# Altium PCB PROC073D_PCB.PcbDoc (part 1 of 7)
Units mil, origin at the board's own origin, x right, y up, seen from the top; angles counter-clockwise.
Board outline 2165.35 x 2695.12 mil, 8 copper layers (Top Layer, L2_GND, L3_SIGNAL 1, L4_SIGNAL 2, L5_SIGNAL 3, L6_SIGNAL 4, L7_GND, Bottom Layer), stack 56.1 mil thick; 414 components, 319 nets, 1353 pads, 1669 vias.
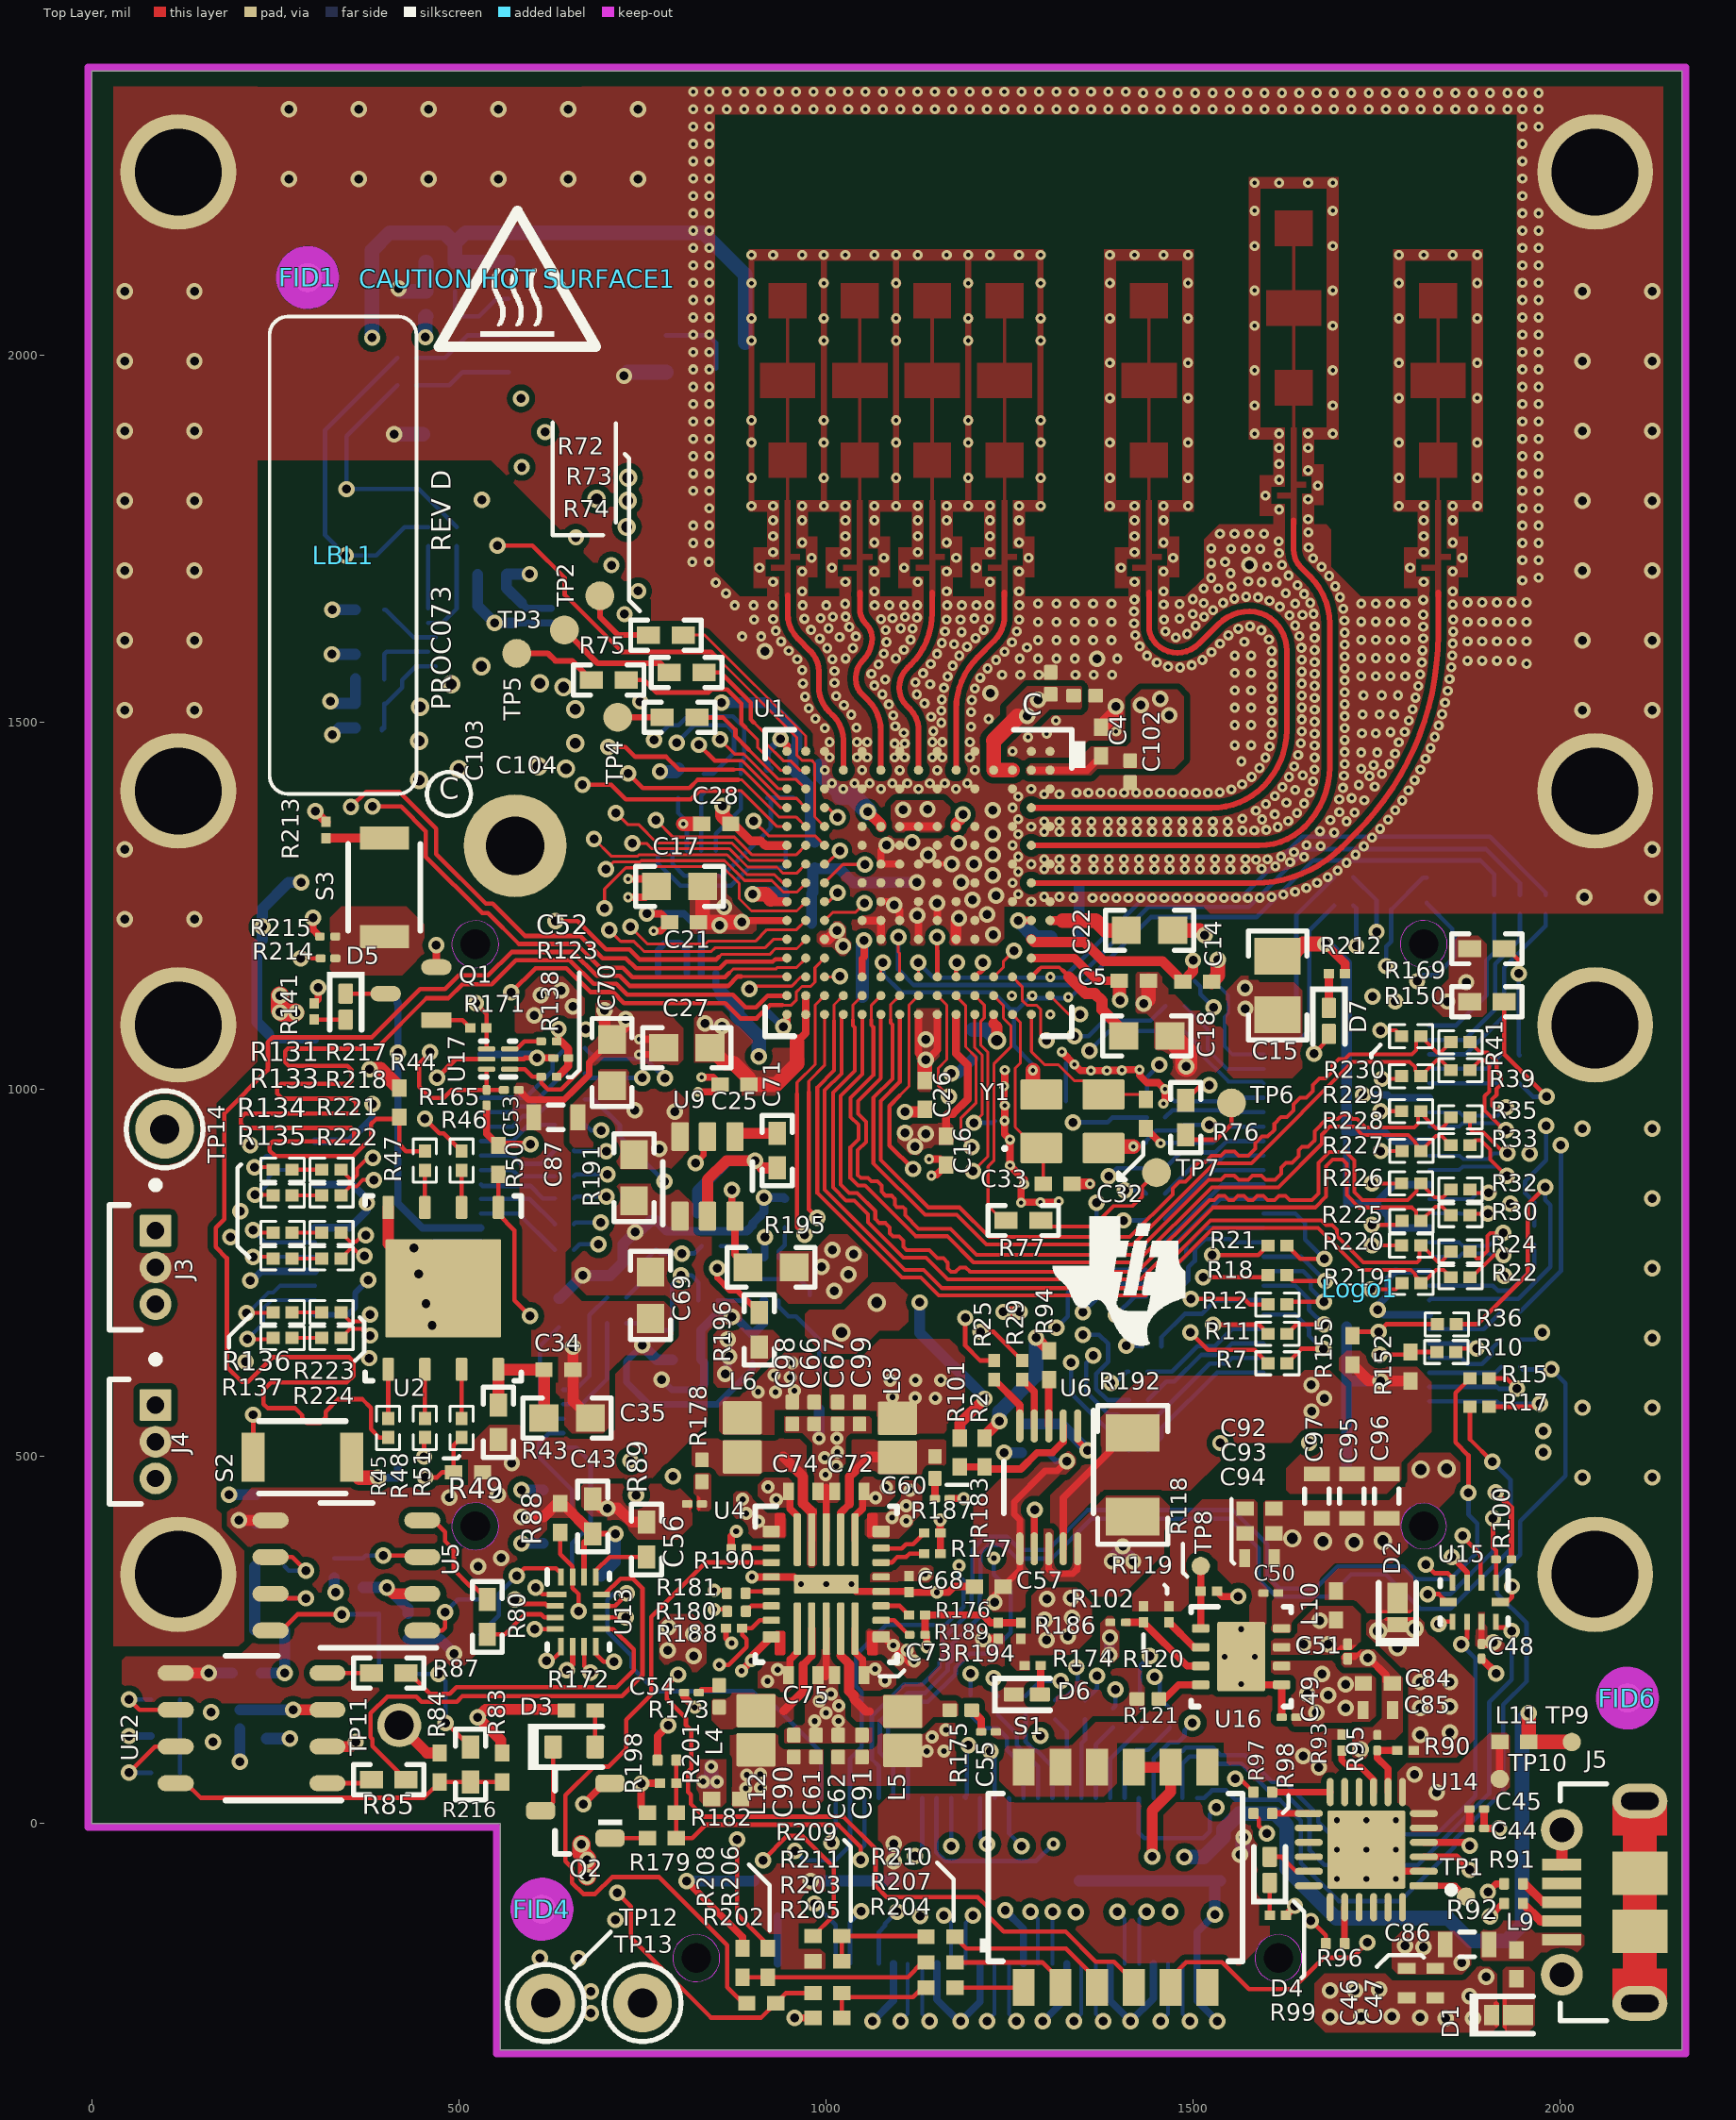
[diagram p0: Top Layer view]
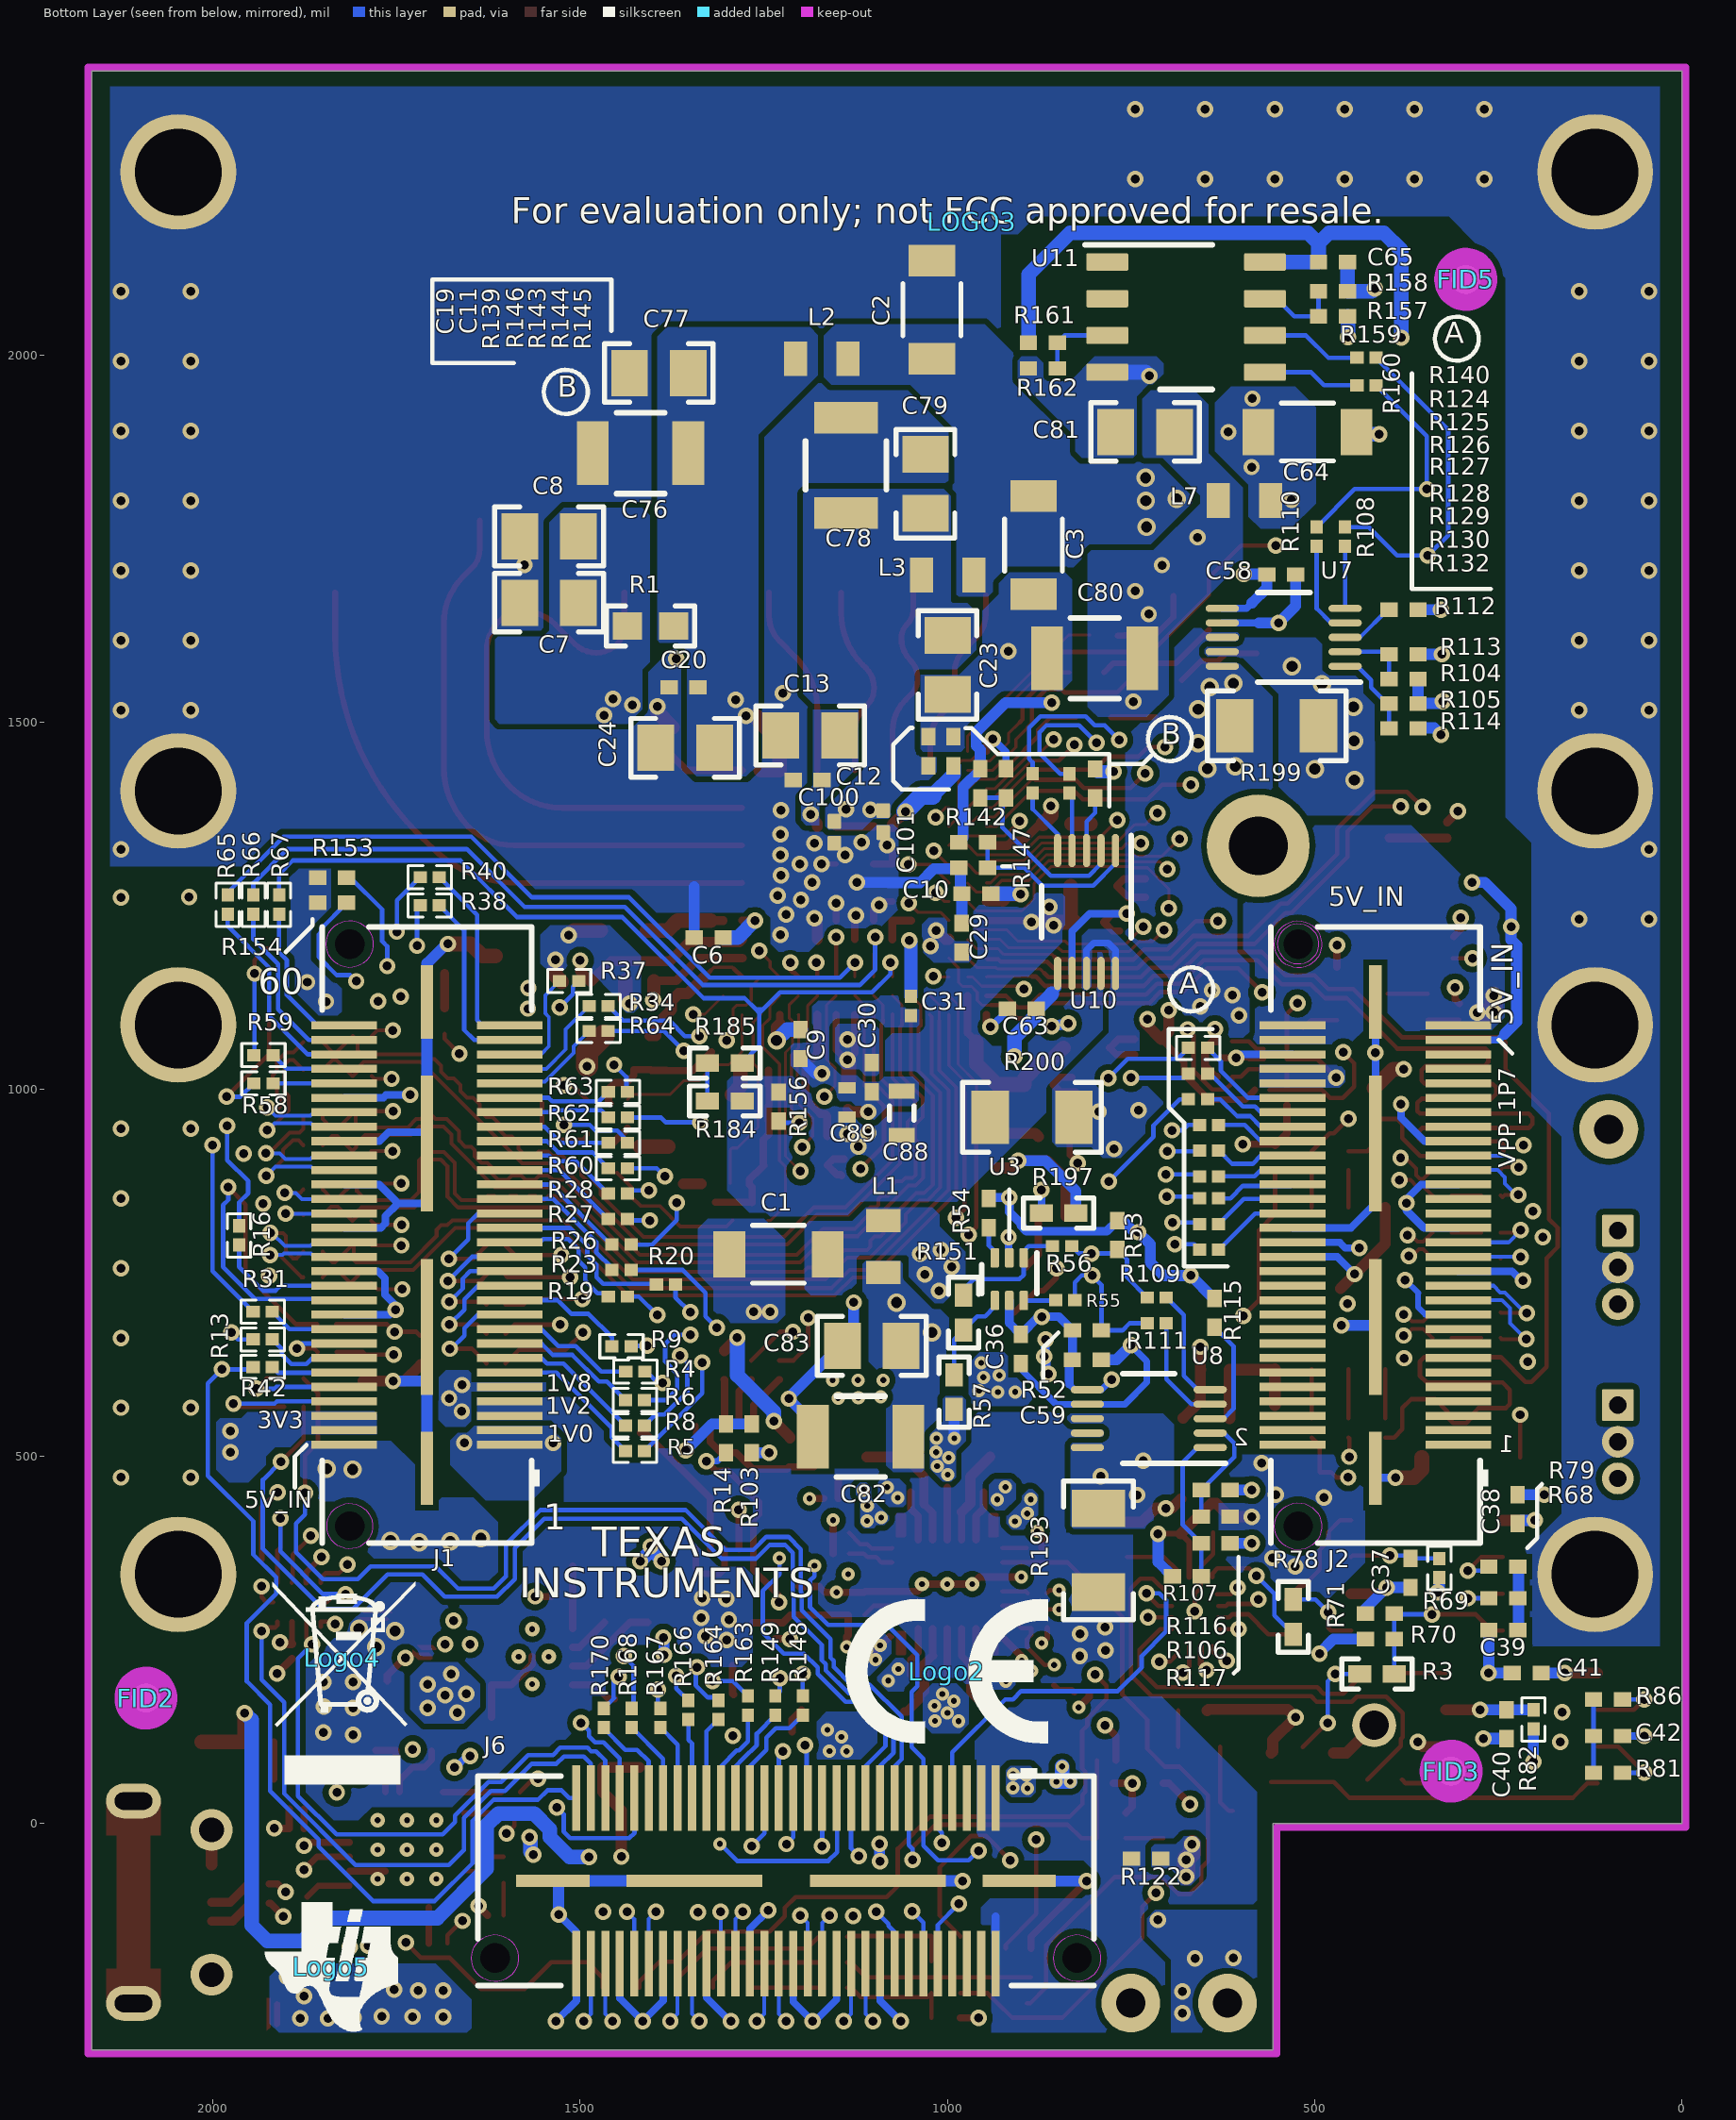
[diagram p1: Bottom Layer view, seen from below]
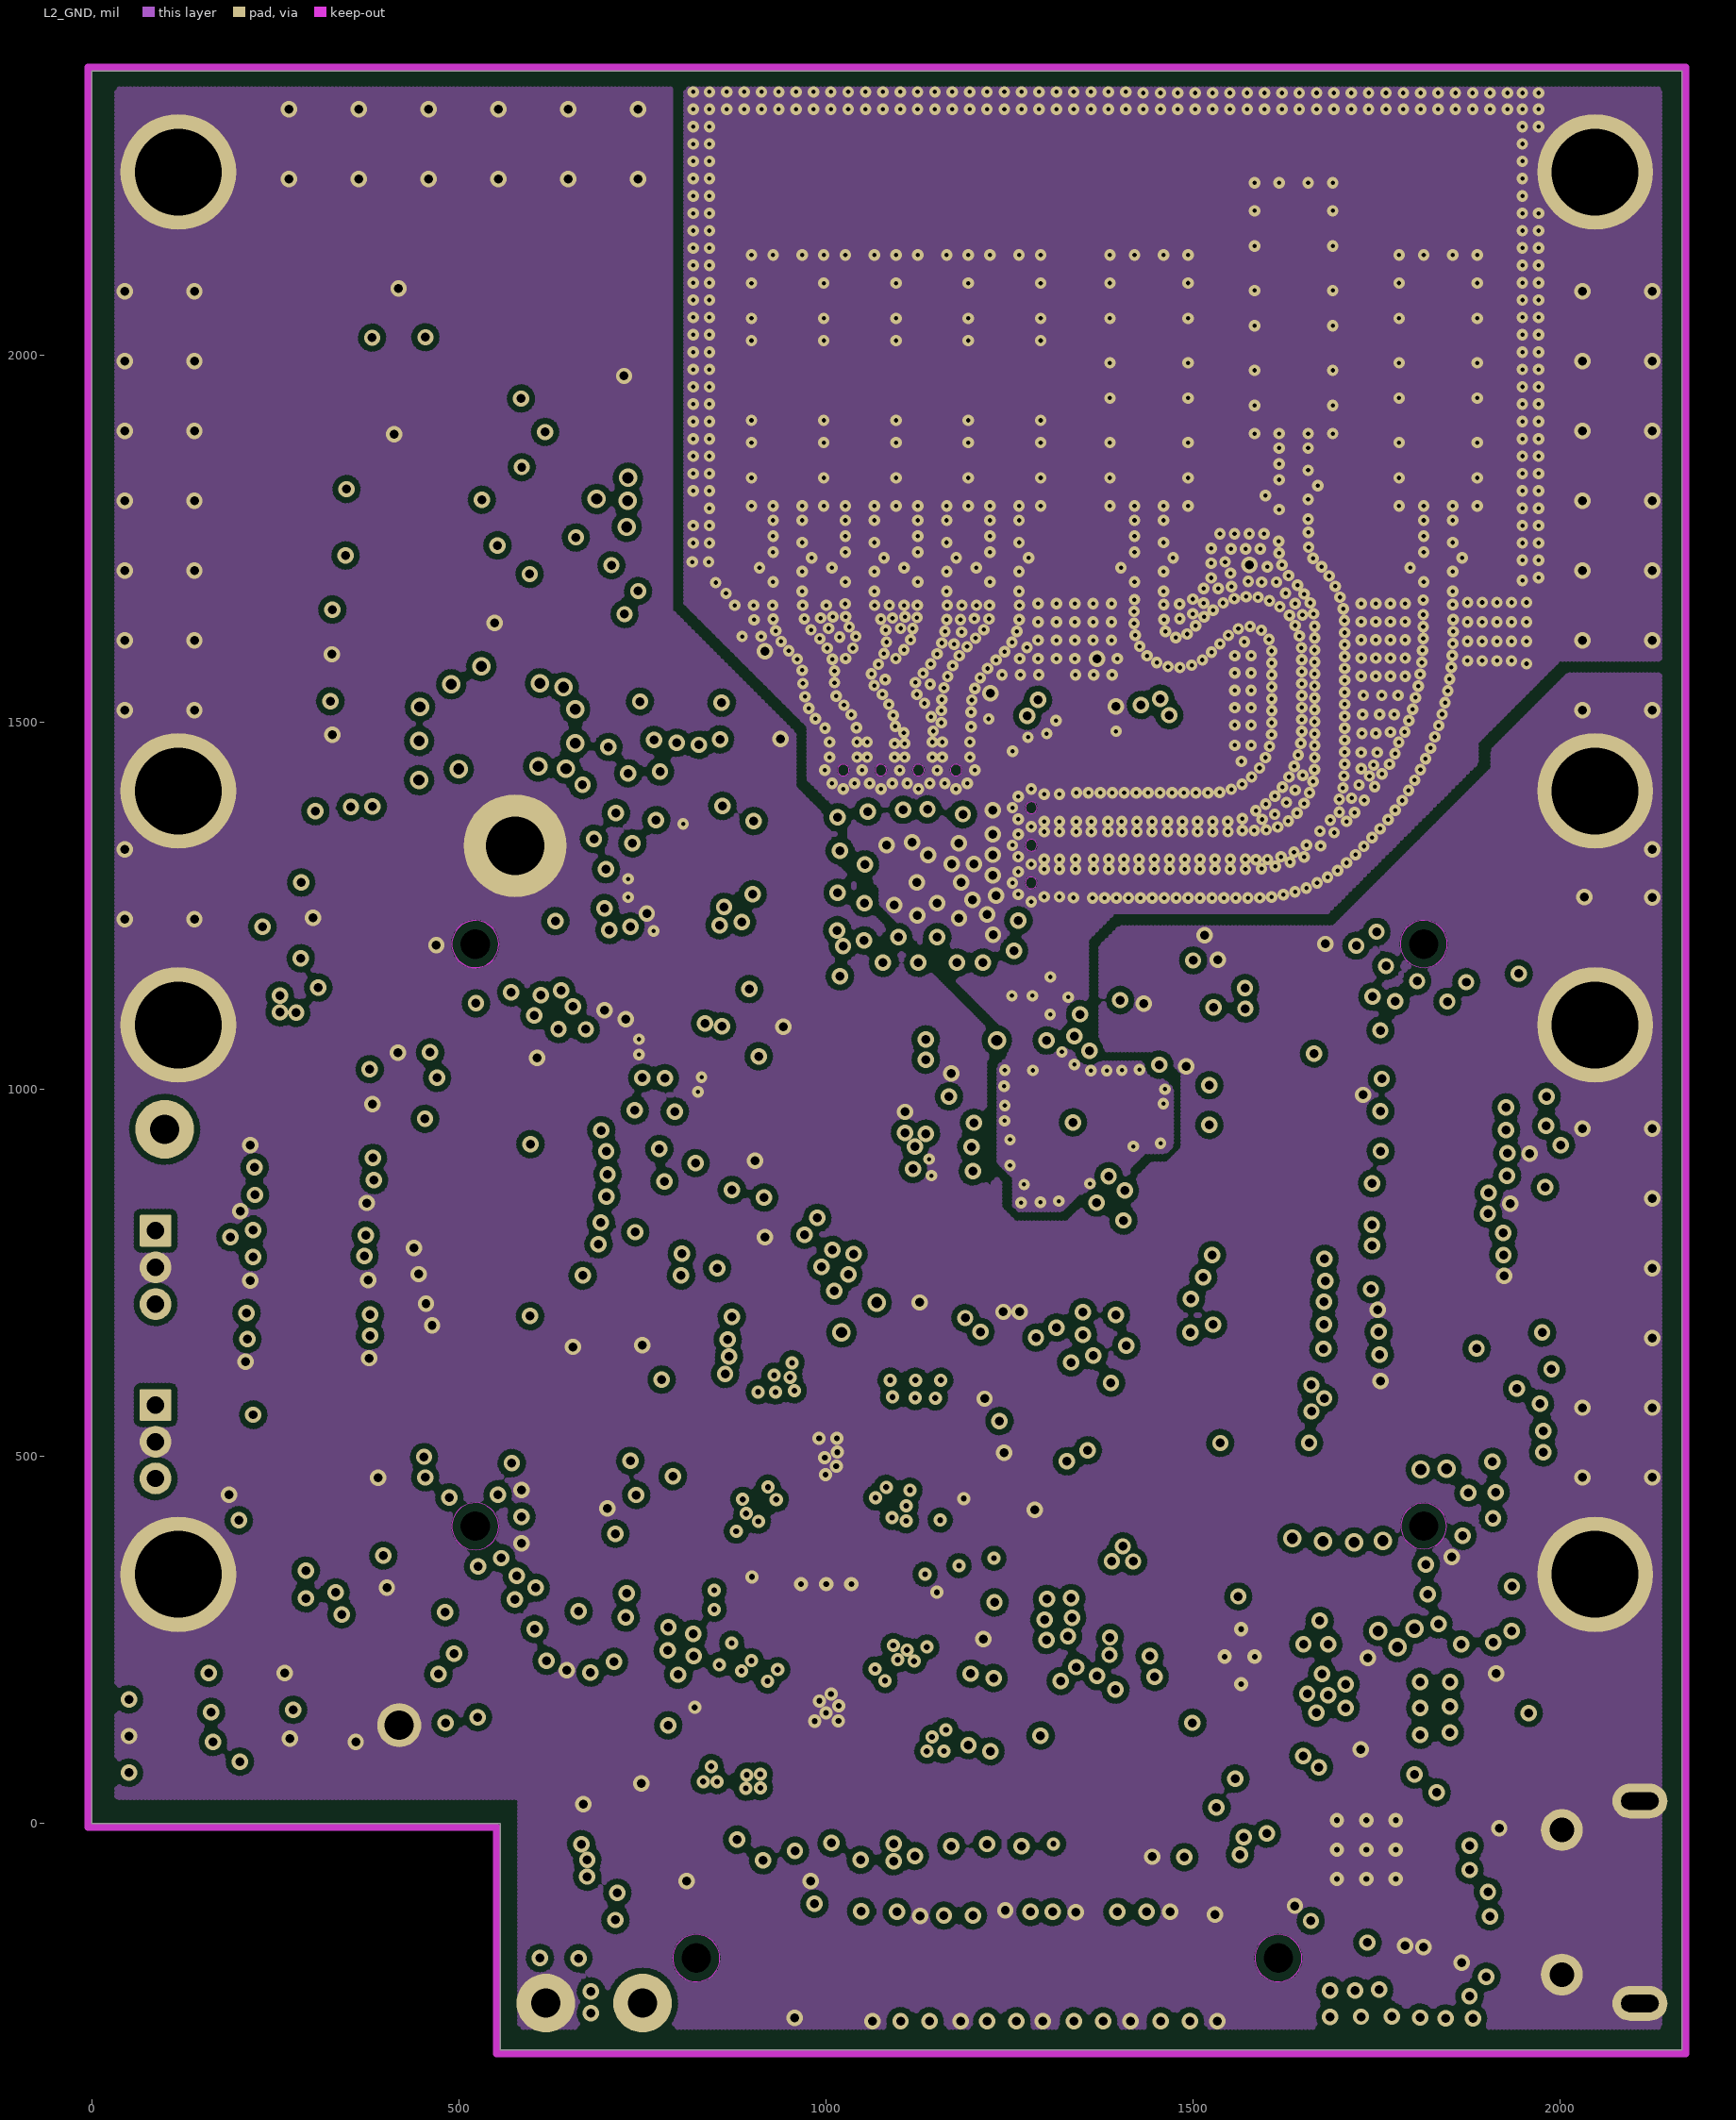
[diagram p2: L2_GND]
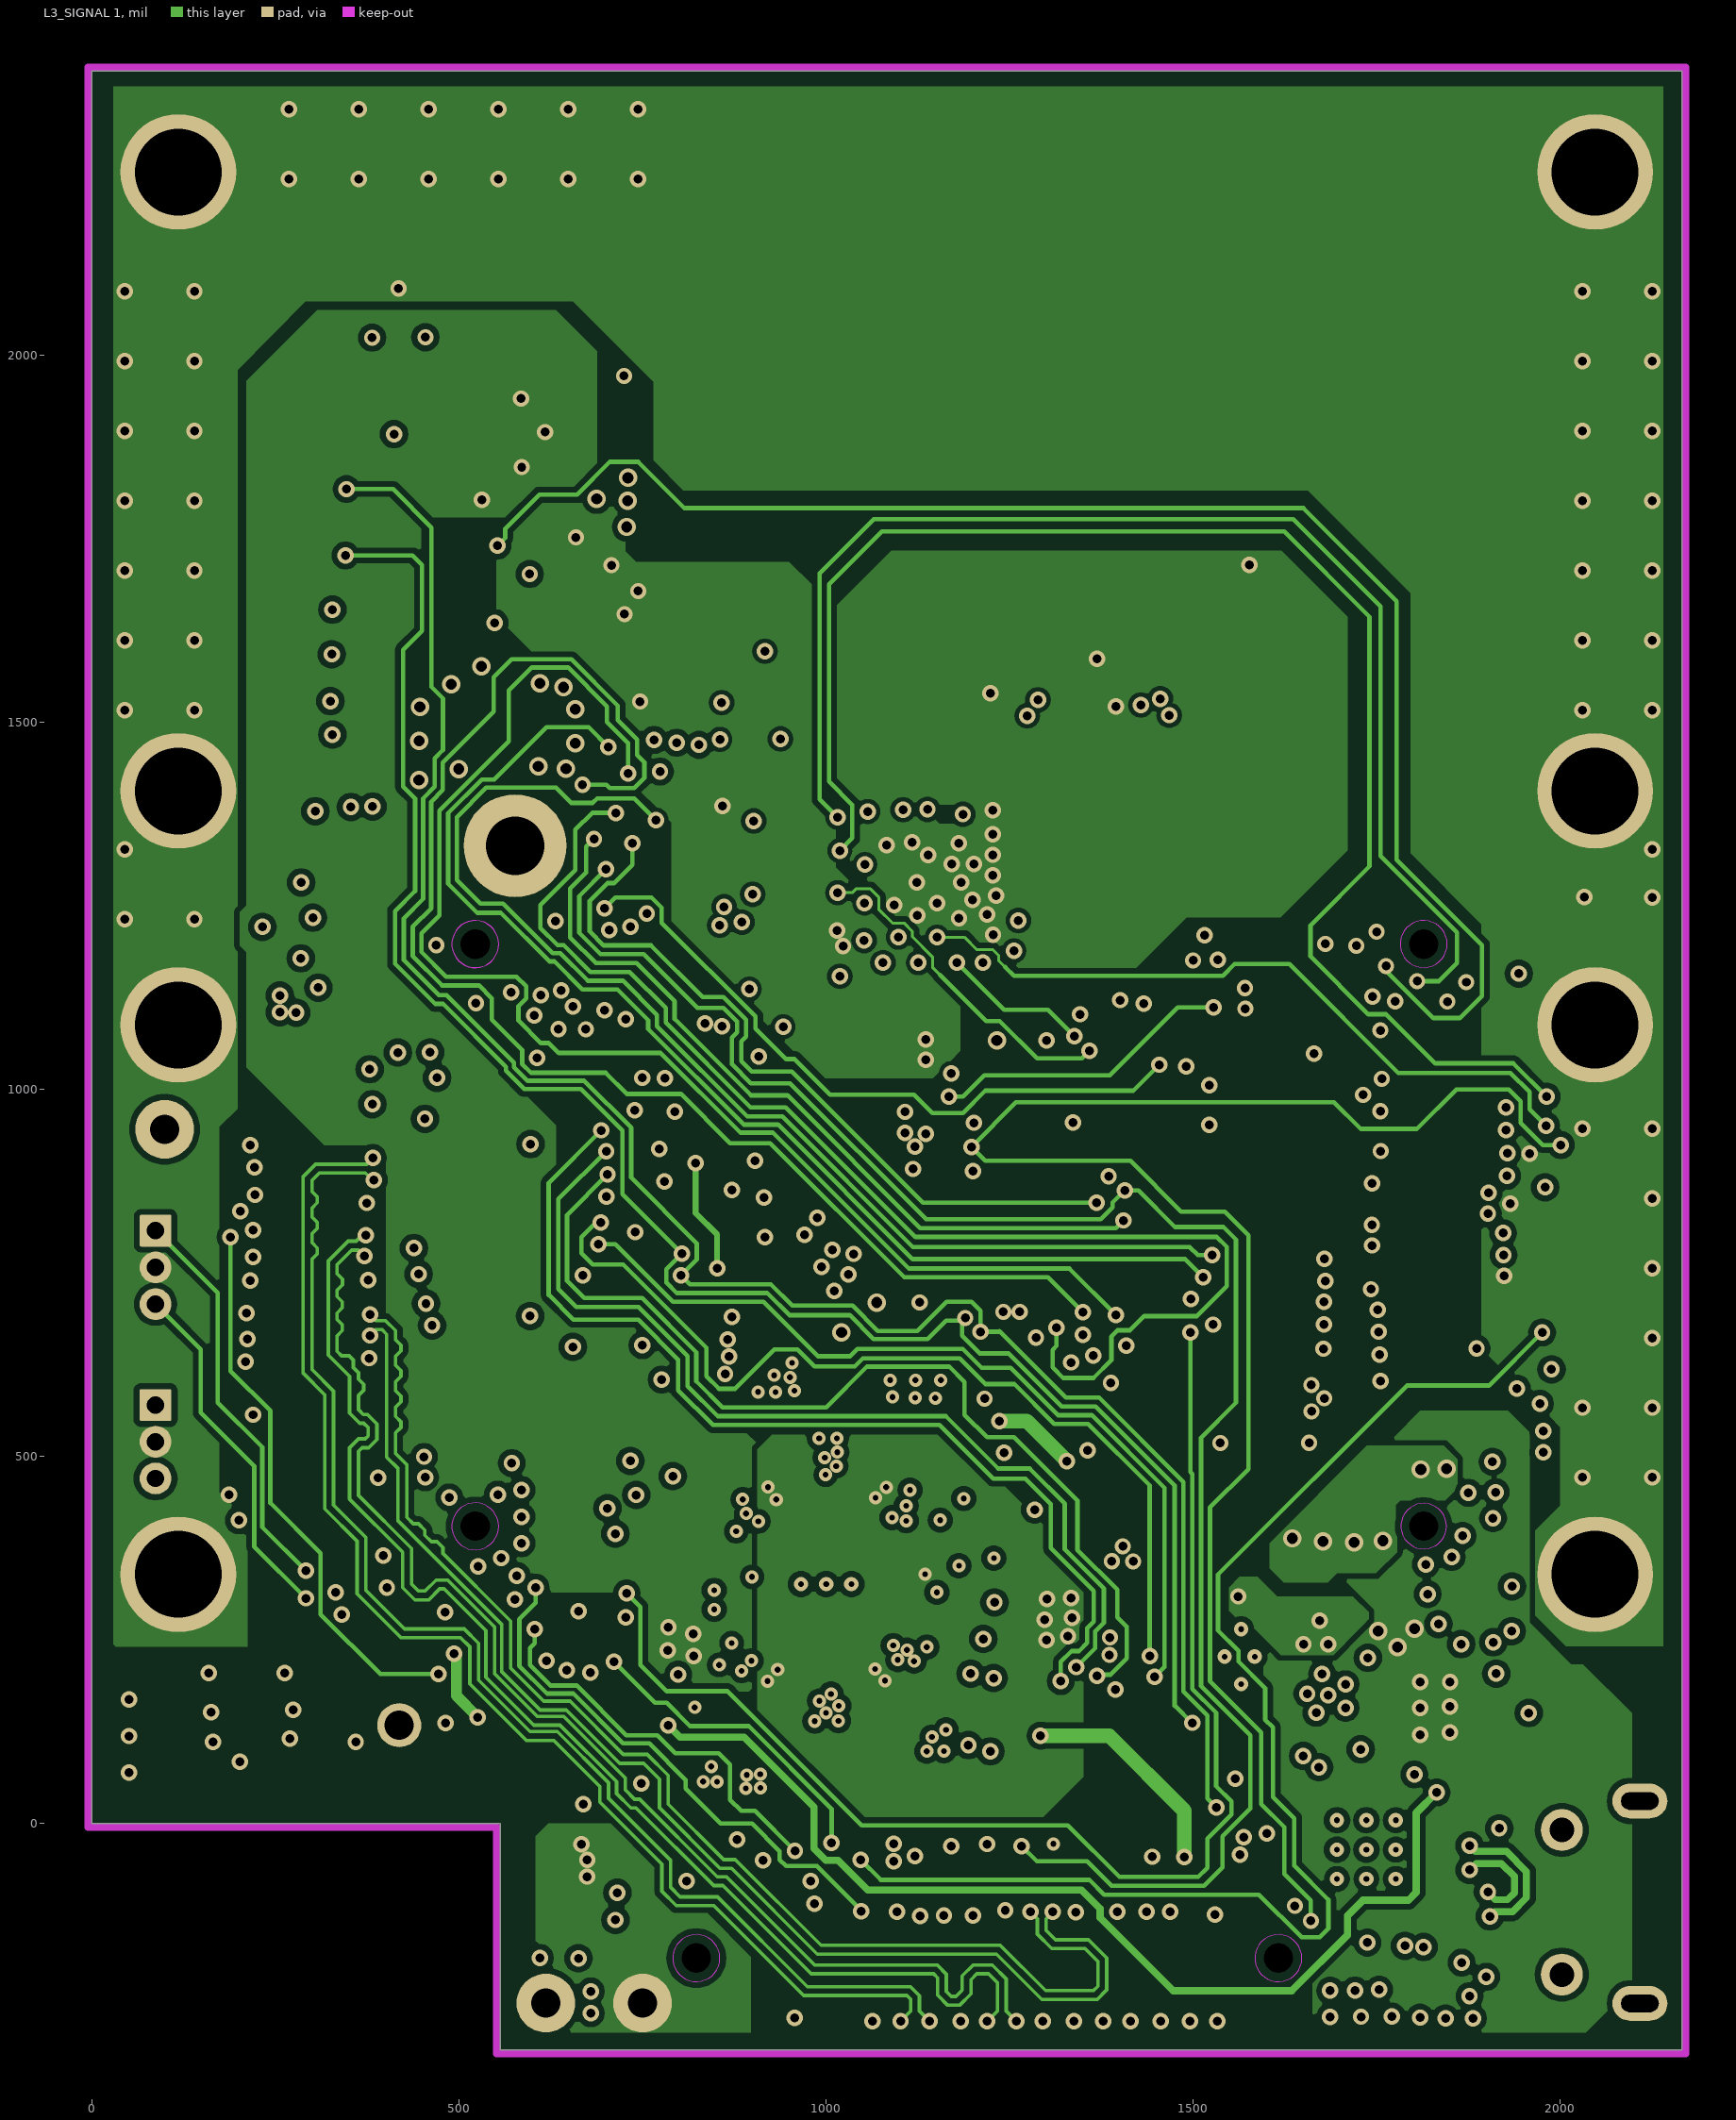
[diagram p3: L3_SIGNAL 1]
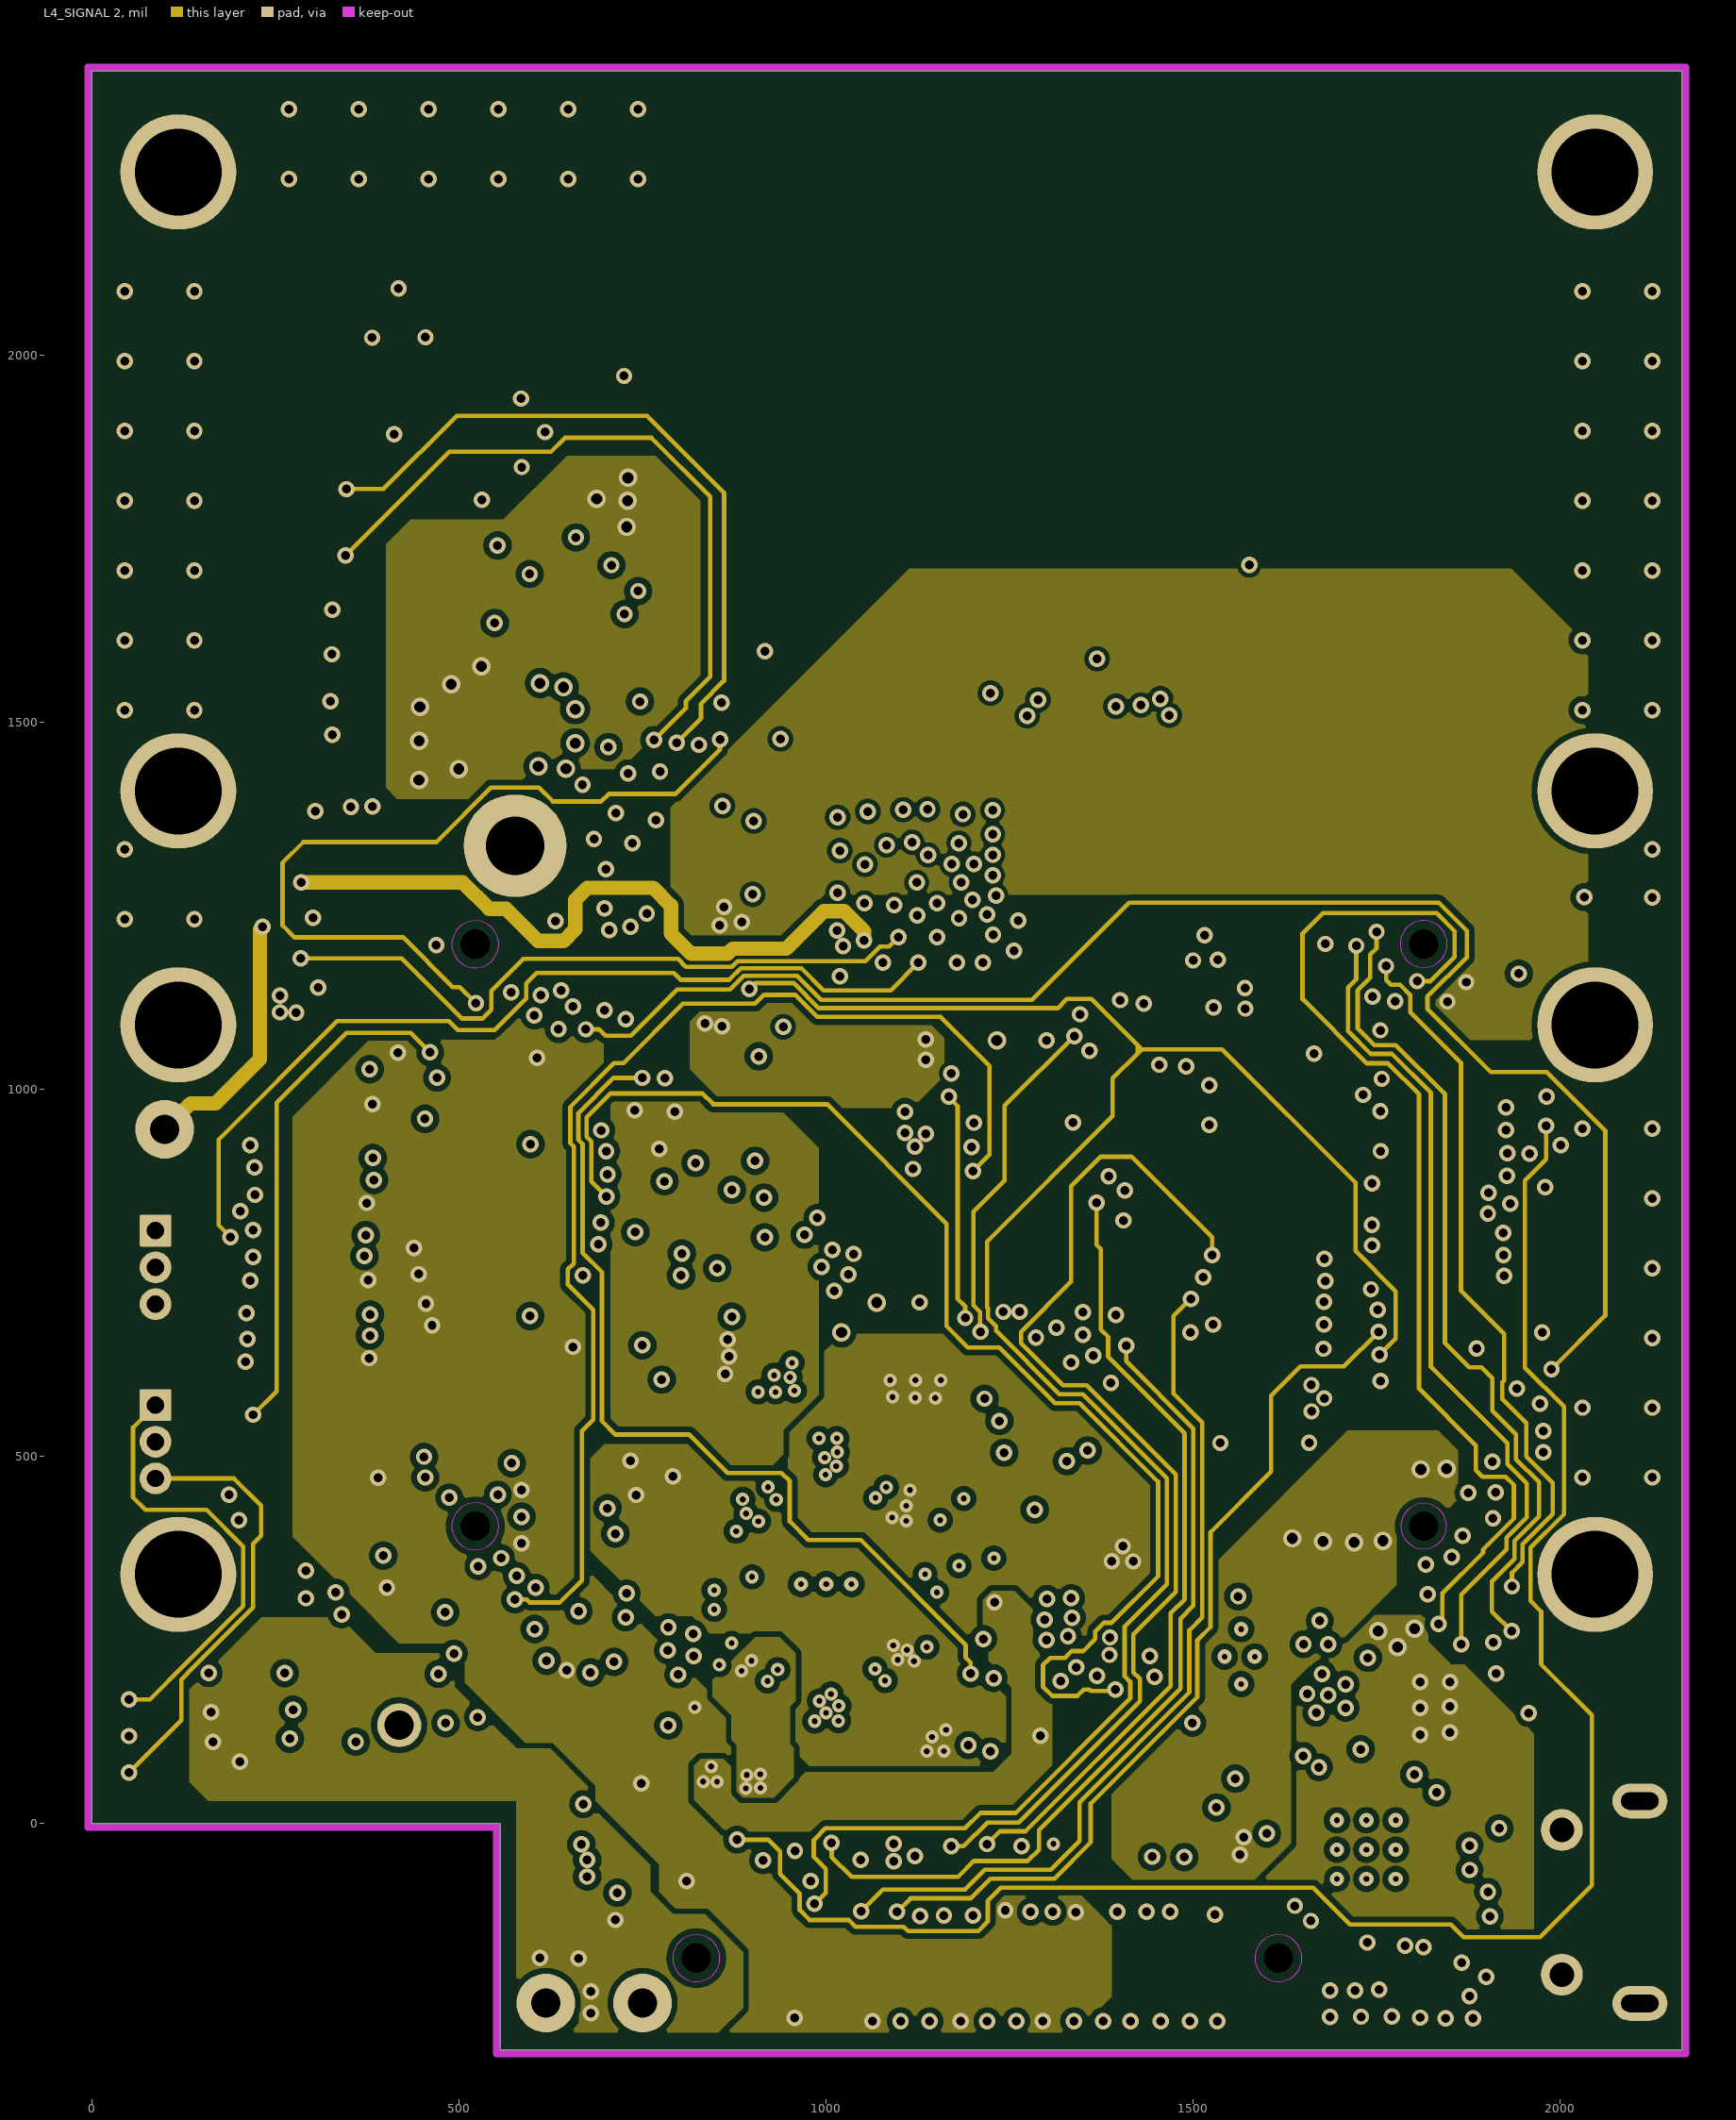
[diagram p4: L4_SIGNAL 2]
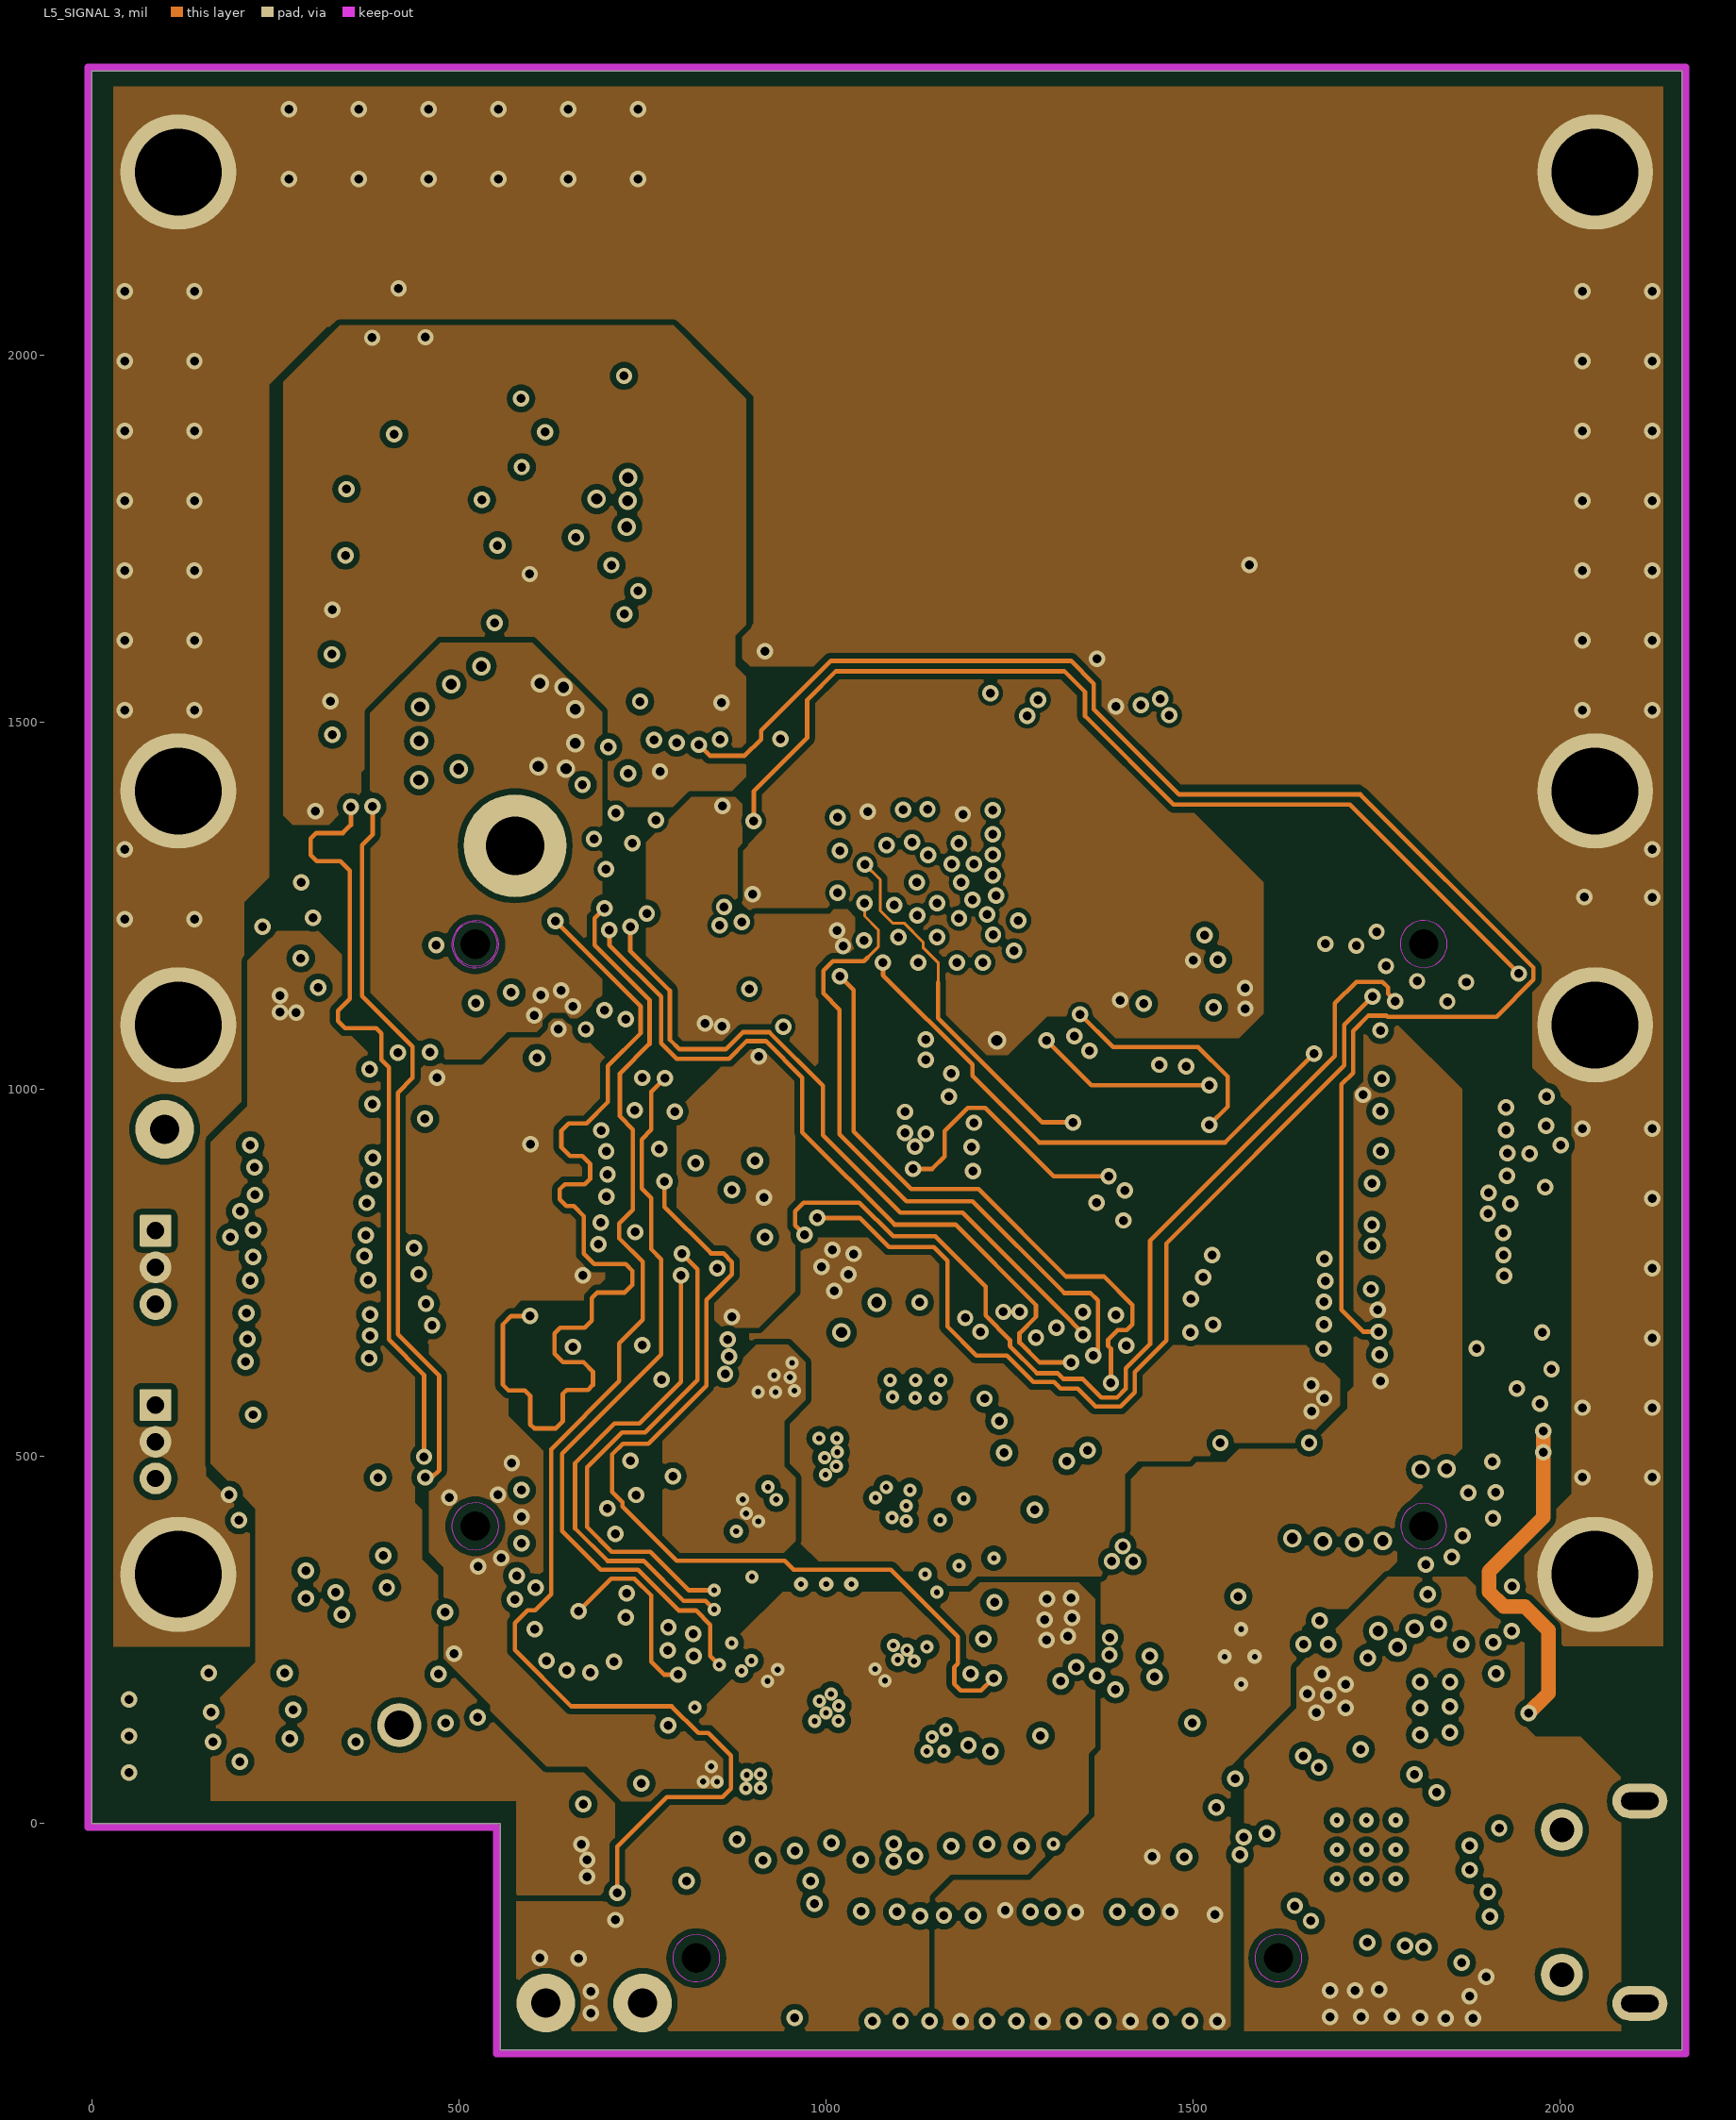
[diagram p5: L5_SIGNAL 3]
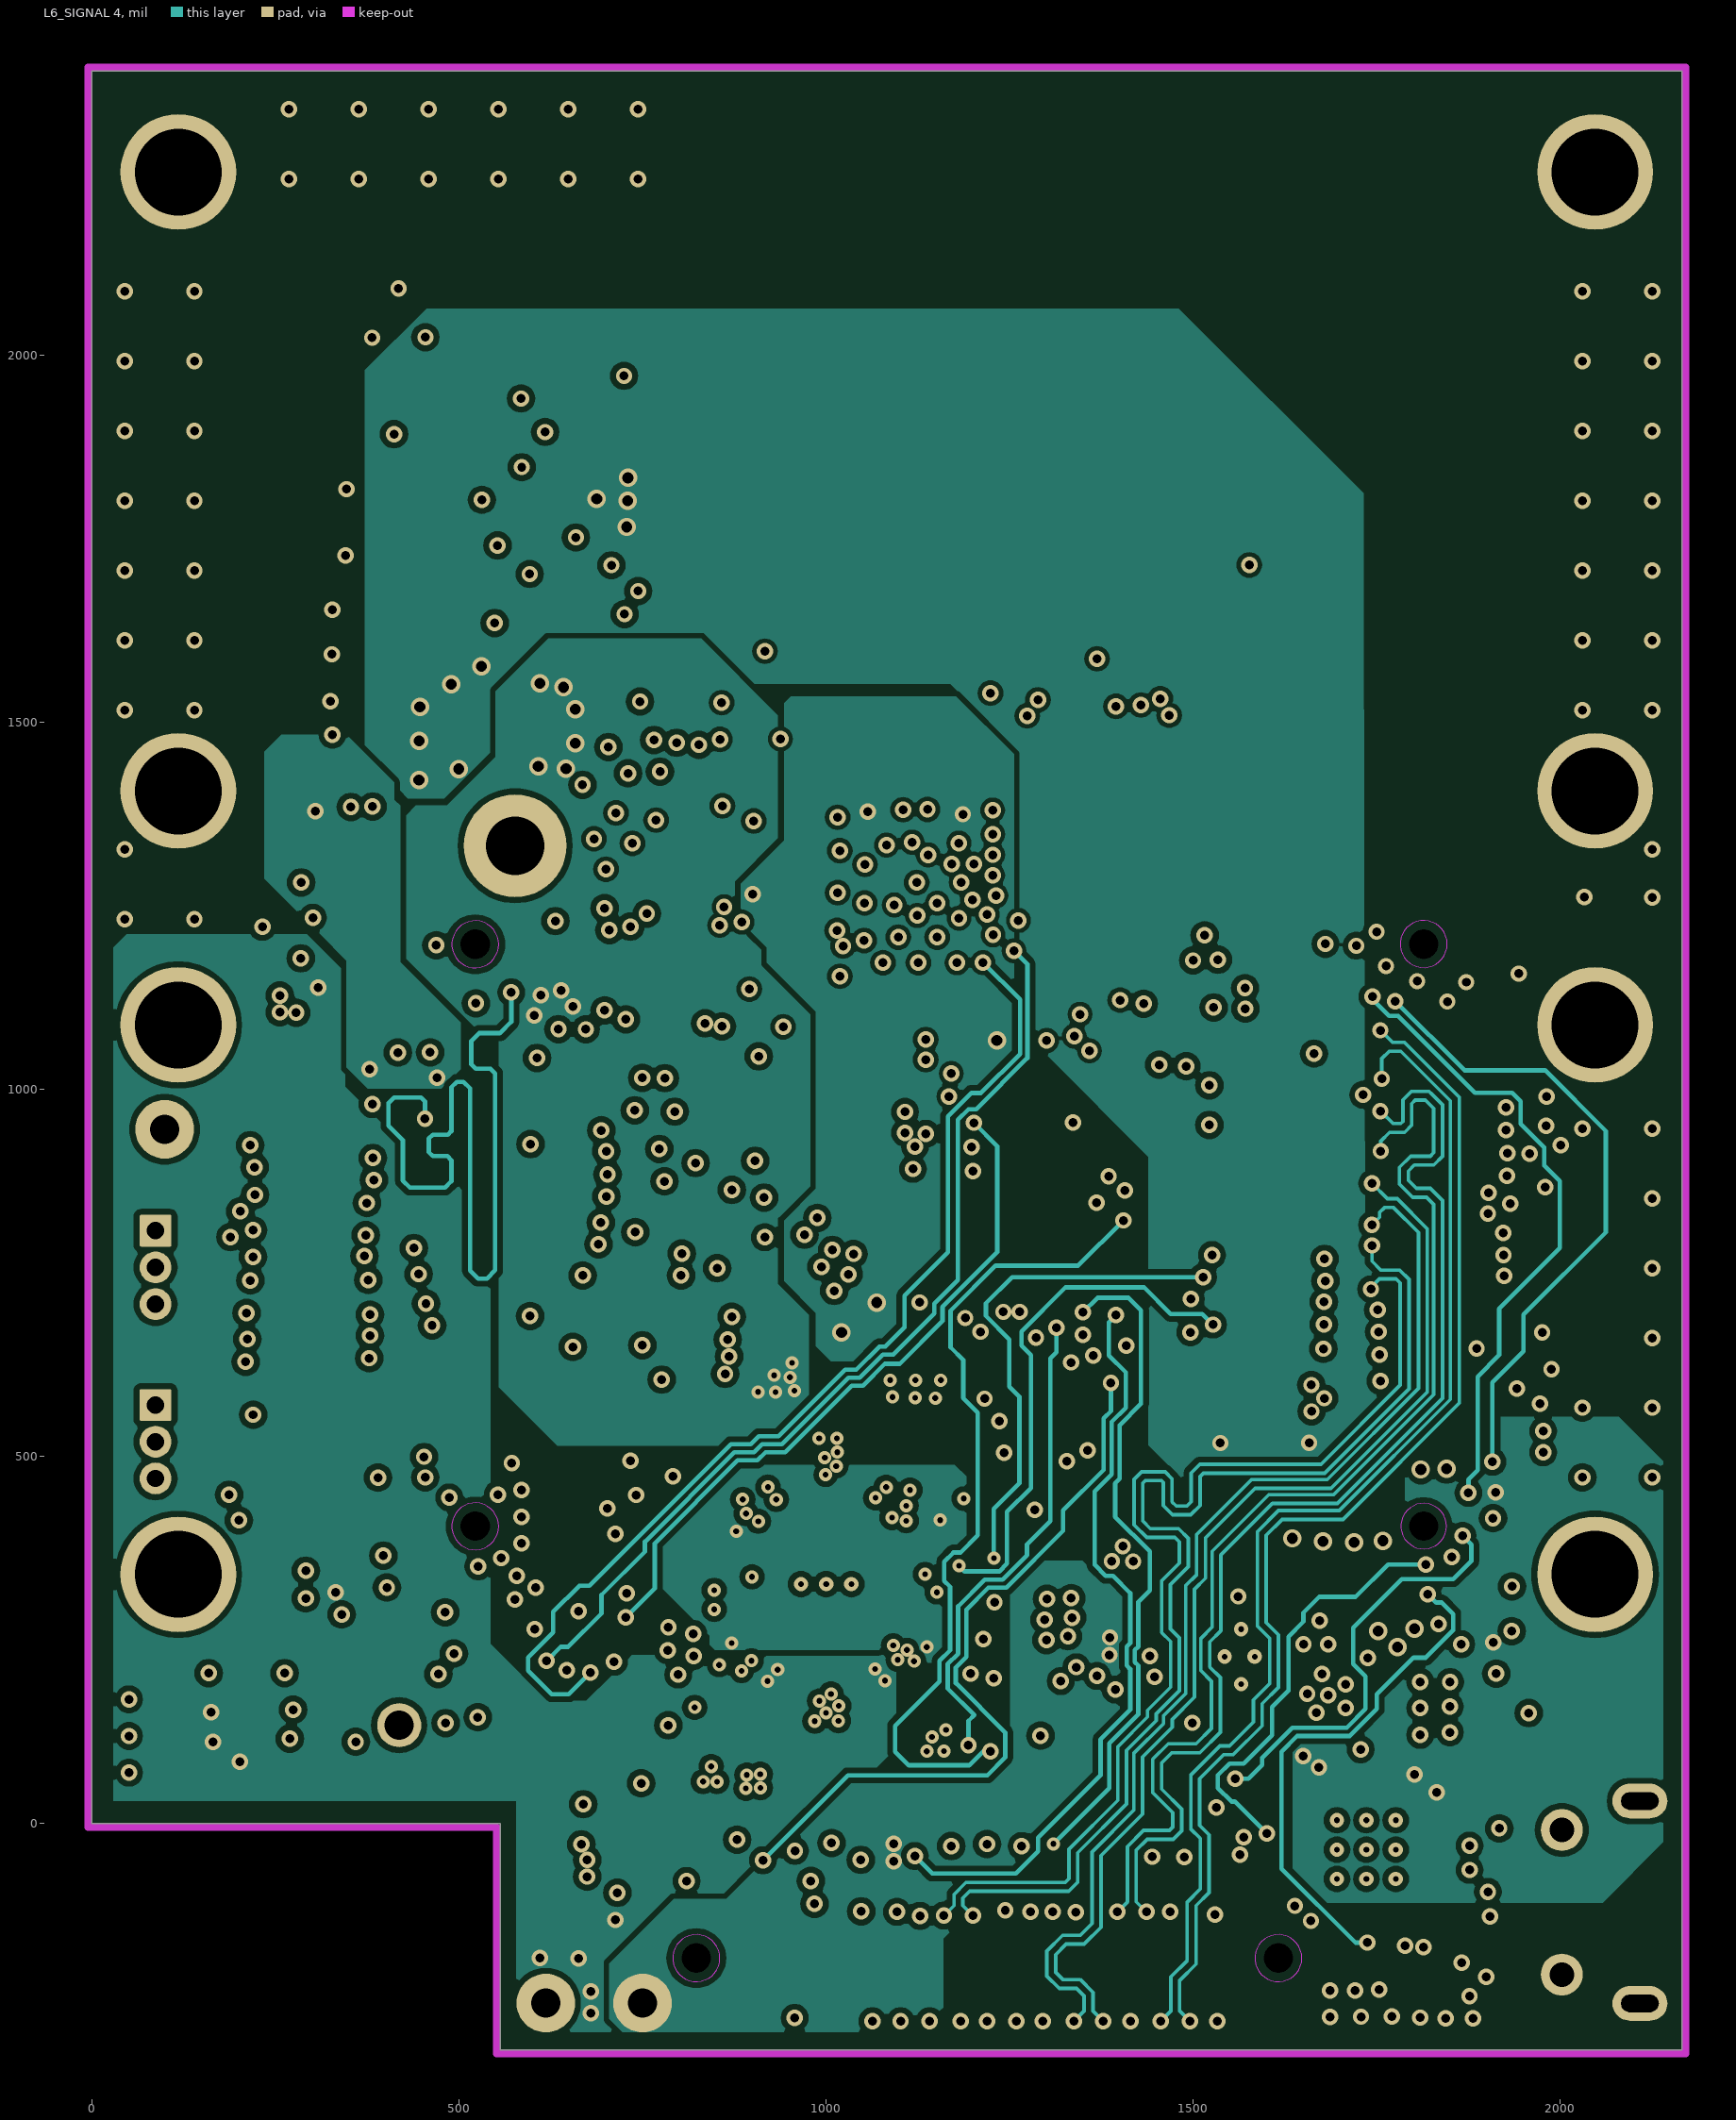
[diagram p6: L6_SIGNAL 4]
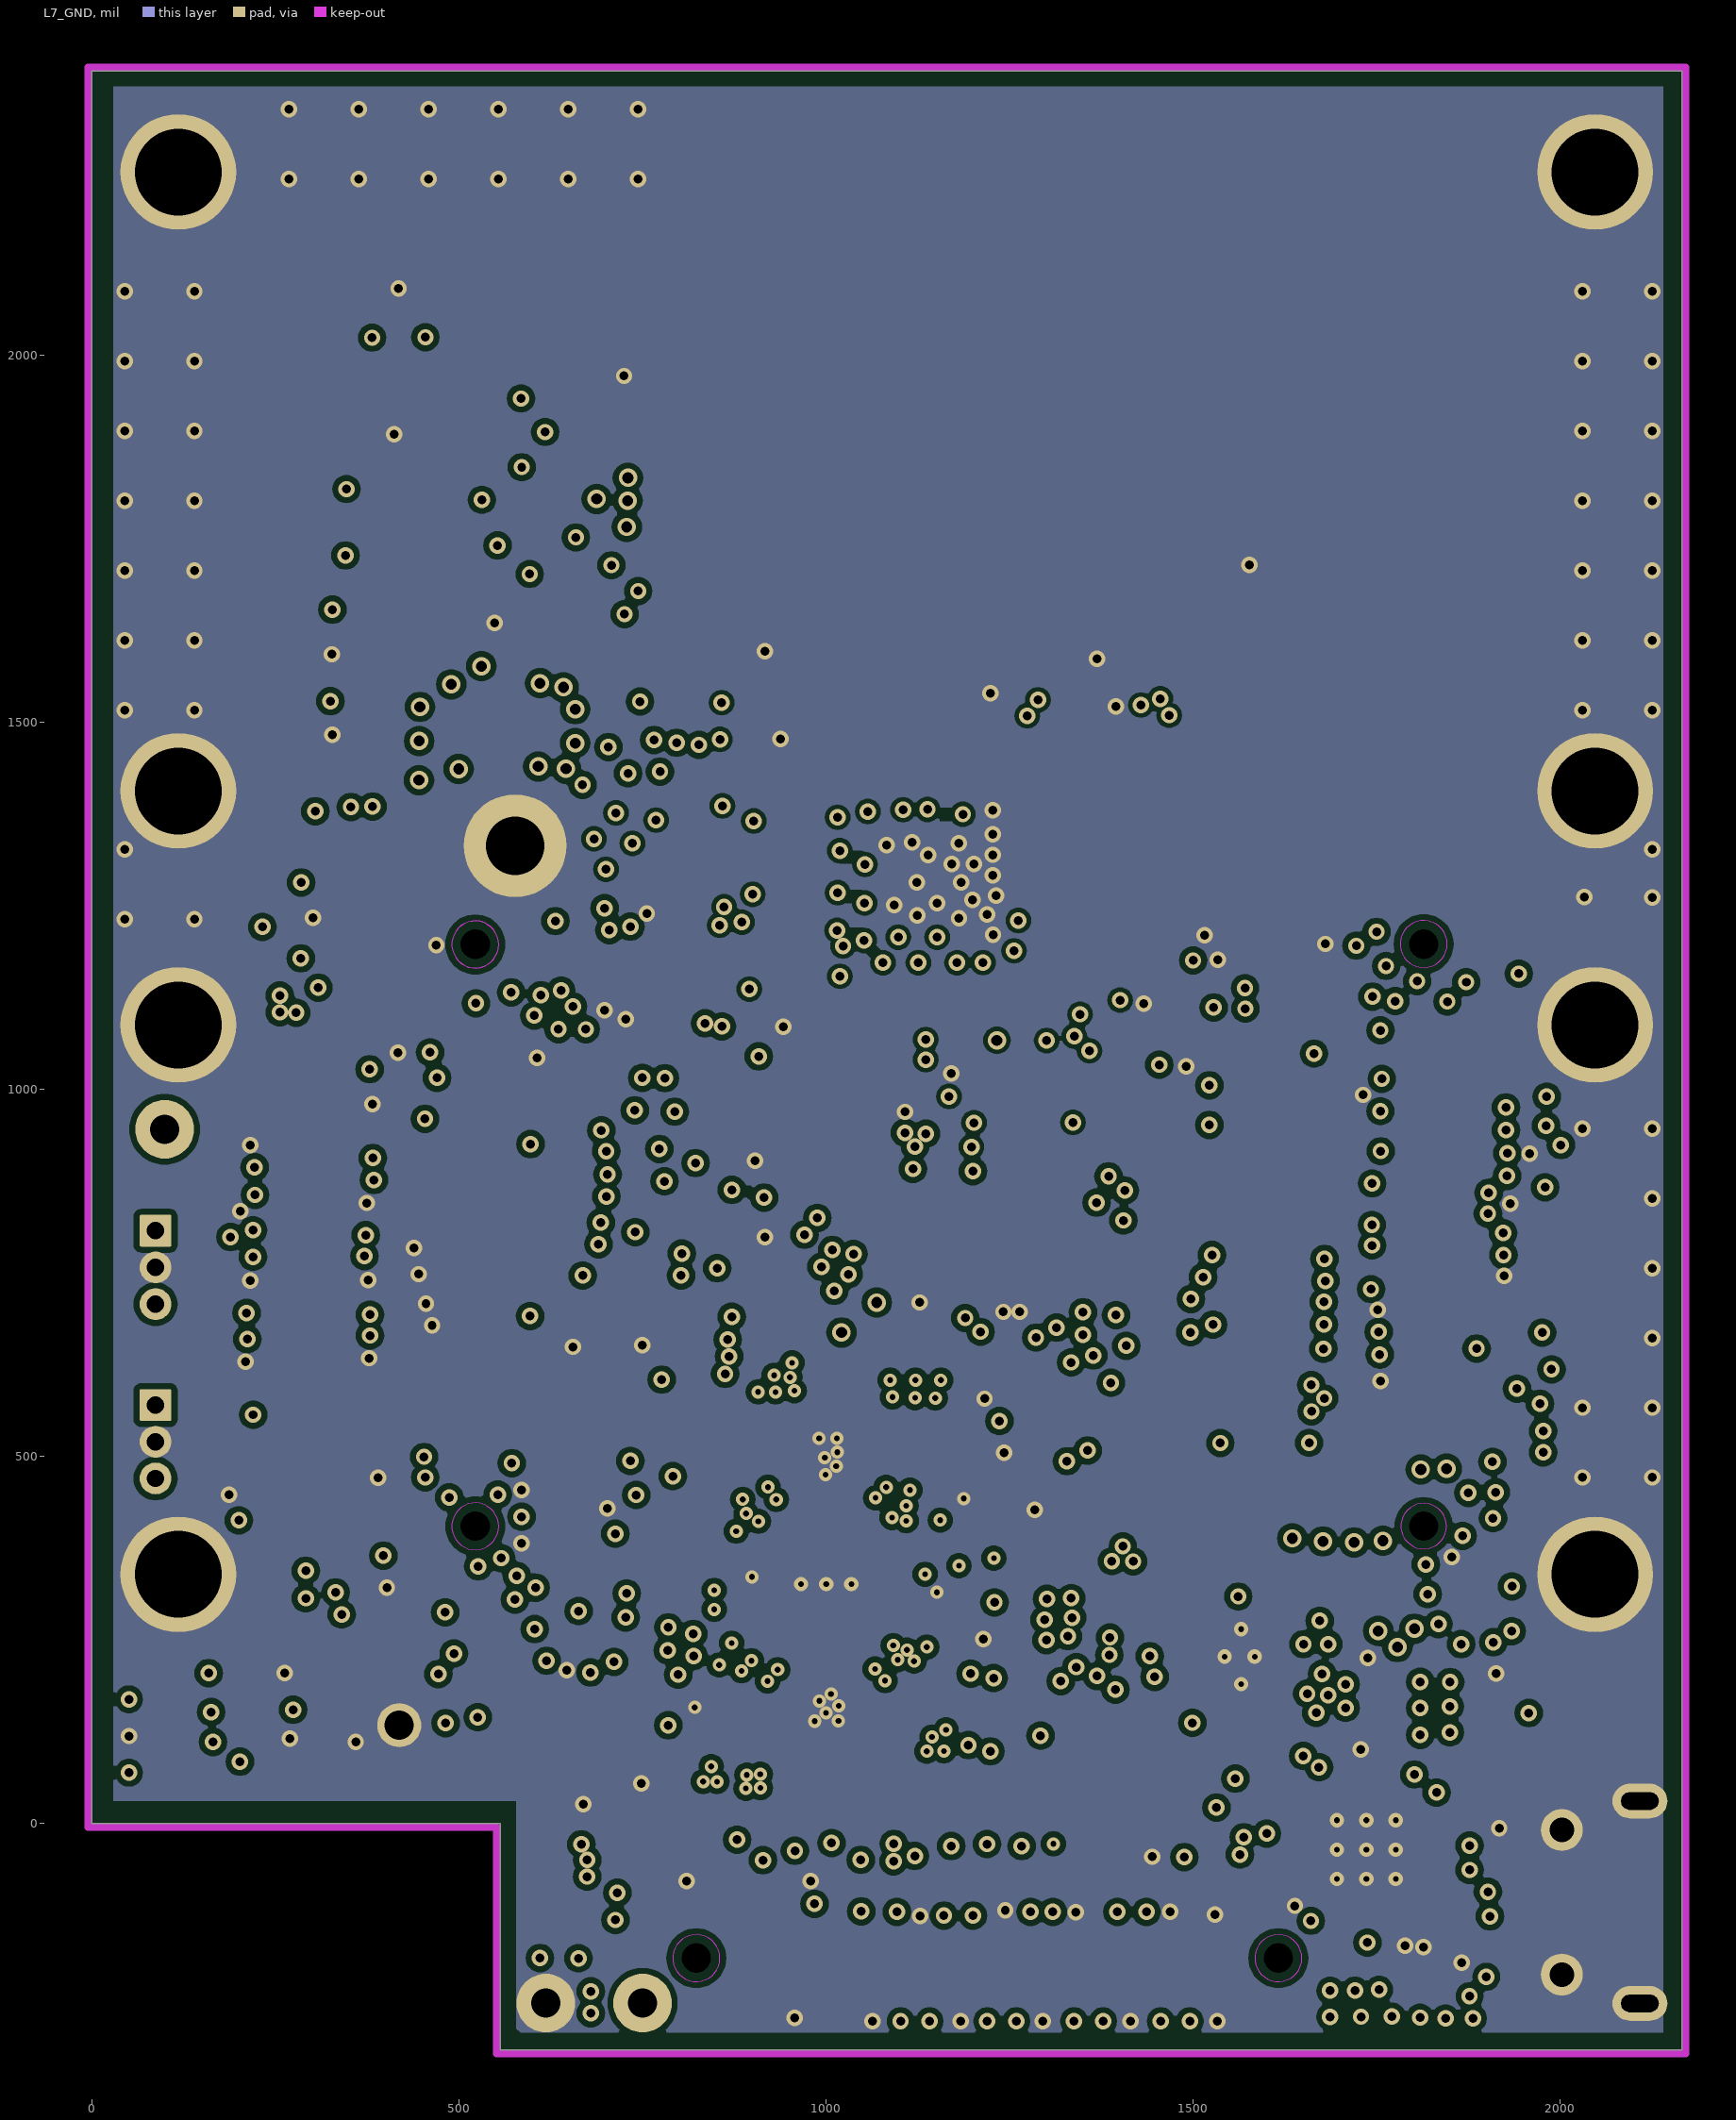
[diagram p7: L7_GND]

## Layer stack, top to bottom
Top Solder: solder mask 0.8, Solder Resist, Dk 1
Top Layer: signal copper 1.6
Dielectric 1: core 4, RO4835 LOPRO, Dk 3.5
L2_GND: signal copper 1.4
Dielectric 2: prepreg 5.5, PCL370HR, Dk 4.17
L3_SIGNAL 1: signal copper 1.4
Dielectric 3: core 10, PCL370HR, Dk 4.17
L4_SIGNAL 2: signal copper 1.4
Dielectric 4: prepreg 5.5, PCL370HR, Dk 4.17
L5_SIGNAL 3: signal copper 1.4
Dielectric 5: prepreg 10, PCL370HR, Dk 4.17
L6_SIGNAL 4: signal copper 1.4
Dielectric 6: core 5.5, PCL370HR, Dk 4.17
L7_GND: signal copper 1.4
Dielectric 7: core 4, PCL370HR, Dk 4.17
Bottom Layer: signal copper 1.6
Bottom Solder: solder mask 0.8, Solder Resist, Dk 1

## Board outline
0,0 556.54,0 556.54,-308.34 2165.35,-308.34 2165.35,2386.78 0,2386.78

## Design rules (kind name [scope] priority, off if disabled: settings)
AcuteAngle [All] p1 off: minimum=4.50000000000000E+0001 checktracksonly=FALSE
AssemblyTestPointUsage [All] p1: valid=2
Clearance Clearance_Fid [IsKeepOut and InComponentClass('FiducialMark') vs IsPad and InComponentClass('FiducialMark')] p1: gap=0 ignorepadtopadclearanceinfootprint=FALSE
Clearance Clearance_KO [IsKeepOut vs IsSMTPin] p2: gap=1 ignorepadtopadclearanceinfootprint=FALSE
Clearance "Clr_L2_GND Cut out (400 Mircrons)" [OnLayer('L2_GND') and InPolygon vs IsKeepOut] p3: gap=0 ignorepadtopadclearanceinfootprint=FALSE except(7: Arc-Arc Arc-Track)
Clearance "Clearance_TX and RX" [InNetClass('TX and RX')] p4: gap=8 ignorepadtopadclearanceinfootprint=FALSE except(0: Arc-Hole Track-Hole SMDPad-Hole THPad-Hole Via-Hole Fill-Hole Poly-Hole Region-Hole Text-Hole; 4: Arc-Text Track-Text SMDPad-Text THPad-Text Via-Text Fill-Text Poly-Text Region-Text Text-Text; 7.7: Fill-Fill Fill-Poly Fill-Region Poly-Poly Poly-Region Region-Region; 7.9: Arc-Via Track-Via; 10: Arc-SMDPad Arc-THPad Track-SMDPad Track-THPad SMDPad-SMDPad SMDPad-THPad SMDPad-Via THPad-THPad THPad-Via)
Clearance Clearance_KO-J5 [IsKeepOut and IsTrack vs InComponent('J5')] p5: gap=19.6 ignorepadtopadclearanceinfootprint=FALSE
Clearance Clearance_Keepout [IsKeepOut and IsTrack] p6: gap=20 ignorepadtopadclearanceinfootprint=FALSE
Clearance Clearance_LVDS_Track [istrack and InNetClass('LVDS') vs istrack and InNetClass('LVDS')] p7: gap=5 ignorepadtopadclearanceinfootprint=FALSE except(3.9: Arc-Arc Arc-Track Track-Track)
Clearance Clearance_LVDS [InNetClass('LVDS') and IsTrack vs (isvia or IsThruPin) and (not InNetClass('LVDS') or not InNet('GND'))] p8: gap=8 ignorepadtopadclearanceinfootprint=FALSE
Clearance Clearance_Region [isregion and incomponent('U4') vs IsTrack] p9: gap=5 ignorepadtopadclearanceinfootprint=FALSE
Clearance "Clr_L1_GND Cut Out (800 Mirons)_1" [OnLayer('L2_GND')] p10: gap=6 ignorepadtopadclearanceinfootprint=FALSE except(0: Arc-Hole Track-Hole SMDPad-Hole THPad-Hole Via-Hole Fill-Hole Poly-Hole Region-Hole Text-Hole; 8: Arc-Fill Arc-Poly Arc-Region Track-Fill Track-Poly Track-Region SMDPad-Fill SMDPad-Poly SMDPad-Region THPad-Fill THPad-Poly THPad-Region Via-Fill Via-Poly Via-Region Fill-Fill Fill-Poly Fill-Region Poly-Poly Poly-Region Region-Region)
Clearance "Clearance_Diff Pairs_LVDS" [InNetClass('Diff Pairs') vs InNetClass('Diff Pairs')] p11: gap=6 ignorepadtopadclearanceinfootprint=FALSE except(0: Arc-Hole Track-Hole SMDPad-Hole THPad-Hole Via-Hole Fill-Hole Poly-Hole Region-Hole Text-Hole; 3.9: Arc-Arc Arc-Track Track-Track; 4: Arc-SMDPad Arc-THPad Arc-Via Track-SMDPad Track-THPad Track-Via; 8: Arc-Fill Arc-Poly Arc-Region Track-Fill Track-Poly Track-Region Via-Fill Via-Poly Via-Region Fill-Fill Fill-Poly Fill-Region Poly-Poly Poly-Region Region-Region)
Clearance "Clr_L1_GND Cut Out (800 Mirons)" [OnTopLayer and InPoly vs IsKeepOut] p12: gap=0 ignorepadtopadclearanceinfootprint=FALSE
Clearance Clearance_BGA [WithinRoom('BGA1')] p13: gap=4 ignorepadtopadclearanceinfootprint=FALSE except(0: Arc-Hole Track-Hole SMDPad-Hole THPad-Hole Via-Hole Fill-Hole Poly-Hole Region-Hole Text-Hole; 1: Arc-SMDPad; 6: SMDPad-Poly THPad-Poly Via-Poly; 7.5: Region-Region; 7.87: Arc-Text Track-Text SMDPad-Text THPad-Text Via-Text Fill-Text Poly-Text Region-Text Text-Text; 8: Arc-Poly Track-THPad Track-Poly THPad-THPad Fill-Poly Poly-Poly)
Clearance [All] p14: gap=8 ignorepadtopadclearanceinfootprint=TRUE except(0: Arc-Hole Track-Hole SMDPad-Hole THPad-Hole Via-Hole Fill-Hole Poly-Hole Region-Hole Text-Hole; 5: Arc-Arc Arc-Track Arc-SMDPad Track-Track Track-SMDPad; 5.1: SMDPad-SMDPad; 6: Arc-THPad Arc-Via Arc-Text Track-THPad Track-Via Track-Text SMDPad-THPad SMDPad-Via SMDPad-Text THPad-THPad THPad-Via THPad-Text Via-Via Via-Text Fill-Text Poly-Text Region-Text Text-Text)
ComponentClearance ComponentClearance_MatingCon-3D [All vs not InAnyComponent] p1: gap=0 collisioncheckmode=3 verticalgap=0 showdistances=FALSE
ComponentClearance "ComponentClearance_WEE Logo" [InComponent('Logo4')] p2: gap=0 collisioncheckmode=3 verticalgap=0 showdistances=TRUE
ComponentClearance ComponentClearance_R77 [InComponent('R77') vs InComponent('Logo1')] p3: gap=0 collisioncheckmode=3 verticalgap=0 showdistances=TRUE
ComponentClearance ComponentClearance_Logo [InComponentClass('Logo')] p4: gap=0 collisioncheckmode=3 verticalgap=0 showdistances=TRUE
ComponentClearance "ComponentClearance_Mounting Holes_Fiducial Marks" [InComponentClass('FiducialMark') vs InPadClass('Mounting Holes PADS')] p5: gap=50 collisioncheckmode=3 verticalgap=10 showdistances=TRUE
ComponentClearance [All] p6: gap=10 collisioncheckmode=3 verticalgap=10 showdistances=TRUE
DiffPairsRouting [All] p1: maxlimit=7.2 minlimit=5 mostfreqgap=7.2 toplayer_maxgap=5 toplayer_prefgap=5 toplayer_minwidth=4 toplayer_maxwidth=5.2 toplayer_prefwidth=5.2 midlayer1_mingap=7.2 midlayer1_minwidth=4.8 midlayer1_maxwidth=4.8 midlayer1_prefwidth=4.8 midlayer2_mingap=7.2 midlayer2_minwidth=4.8 midlayer2_maxwidth=4.8 midlayer2_prefwidth=4.8 midlayer3_mingap=7.2 midlayer3_minwidth=4.8 midlayer3_maxwidth=4.8 midlayer3_prefwidth=4.8 midlayer4_mingap=7.2 midlayer4_minwidth=4.8 midlayer4_maxwidth=4.8 midlayer4_prefwidth=4.8 midlayer5_mingap=7.2 midlayer5_minwidth=4.8 midlayer5_maxwidth=4.8 midlayer5_prefwidth=4.8 midlayer6_mingap=7.2 midlayer6_minwidth=4.8 midlayer6_maxwidth=4.8 midlayer6_prefwidth=4.8 bottomlayer_maxgap=5 bottomlayer_prefgap=5 bottomlayer_minwidth=5.2 bottomlayer_maxwidth=5.2 bottomlayer_prefwidth=5.2 maxuncoupledlength=500
FabricationTestPointUsage TestPointUsage [All] p1: valid=2 allowmultiple=FALSE
FabricationTestpoint Testpoint [All] p1: side=3 testpointundercomponent=TRUE minsize=40 maxsize=100 preferedsize=60 minholesize=0 maxholesize=40 preferedholesize=32 testpointgrid=1 allowsidetop=TRUE allowsidebottom=TRUE usegrid=TRUE gridtolerance=0.01
FanoutControl Fanout_LCC [IsLCC] p1: bgadir=Out bgaviamode=Centered fanoutstyle=Auto fanoutdirection=Alternating viagrid=1 // Fanout_LCC (Default Rule)
FanoutControl Fanout_BGA [IsBGA] p2: bgadir=Out bgaviamode=Centered fanoutstyle=Auto fanoutdirection=Alternating viagrid=1 // Fanout_BGA (Default Rule)
FanoutControl Fanout_Default [All] p4: bgadir=Out bgaviamode=Centered fanoutstyle=Auto fanoutdirection=Alternating viagrid=1 // Fanout_Default (Default Rule)
FanoutControl Fanout_Small [(CompPinCount < 5)] p5: bgadir=Out bgaviamode=Centered fanoutstyle=Auto fanoutdirection=OutThenIn viagrid=1 // Fanout_Small (Default Rule)
Height Room_Hieght [WithinRoom('Room_Hieght 1 MM')] p1: minheight=0 maxheight=41.34 prefheight=39.37
HoleSize [All] p1: absolutevalues=TRUE maxlimit=280 minlimit=5.9 maxpercent=80.000 minpercent=20.000
HoleToHoleClearance HoleToHoleClearance_1 [InDrillLayerPair('Top Layer - L2_GND') vs InDrillLayerPair('Top Layer - L2_GND')] p1: gap=7.7 allowstackedmicrovias=TRUE
HoleToHoleClearance [All] p2: gap=8 allowstackedmicrovias=TRUE
MatchedLengths MatchedLengths_SPI [InxSignalClass('SPI')] p1: tolerance=2 checknetsindiffpair=FALSE checkdiffpairvsdiffpair=TRUE checkxsignals=TRUE checkothers=TRUE
MatchedLengths MatchedLengths-J2-J6 [InxSignalClass('J2-J6')] p2: tolerance=15 checknetsindiffpair=FALSE checkdiffpairvsdiffpair=TRUE checkxsignals=TRUE checkothers=TRUE
MatchedLengths MatchedLengths_U1-J6 [InxSignalClass('U1-J6')] p3: tolerance=15 checknetsindiffpair=FALSE checkdiffpairvsdiffpair=TRUE checkxsignals=TRUE checkothers=TRUE
MatchedLengths MatchedLengths-U1-J1 [InxSignalClass('U1-J1')] p4: tolerance=15 checknetsindiffpair=FALSE checkdiffpairvsdiffpair=TRUE checkxsignals=TRUE checkothers=TRUE
MatchedLengths MatchedLengths_Pairs [InxSignalClass('All xSignals')] p5: tolerance=10 checknetsindiffpair=TRUE checkdiffpairvsdiffpair=FALSE checkxsignals=FALSE checkothers=FALSE
MinimumAnnularRing MinimumAnnularRing_ThermalPadVias [IsVia and InAnyComponent] p1: minimumring=3.9
MinimumAnnularRing [All] p2: minimumring=3.9
MinimumSolderMaskSliver MinimumSolderMaskSliver_Logo [InComponentClass('Logo') vs InComponentClass('Logo')] p1: minsoldermaskwidth=0.7
MinimumSolderMaskSliver [All] p2: minsoldermaskwidth=3.5
PlaneConnect [All] p1: planeconnectstyle=Relief reliefexpansion=10 reliefentries=4 reliefconductorwidth=10 reliefairgap=10
PolygonConnect [All] p1: connectstyle=Direct reliefconductorwidth=10 reliefentries=4 polygonreliefangle="90 Angle" airgapwidth=10
RoomDefinition BGA1 [WithinRoom('BGA1')] p1: confinementstyle=ConfineIn formatcopy=TRUE lockcomponents=FALSE outline 830,2365.43 1999.28,2365.43 1999.28,1605.71 1921,1527.43 1921,1493.43 1663,1235.43 1415,1235.43 1414,1234.43 1414,1061.43 1477,998.43 1477,914.43 1467,904.43 1435,904.43 1418,887.43 1362,887.43 1362,841.43 1345,824.43 1266,824.43 1256,834.43 1256,868.43 1224,900.43 1190,900.43 1177,913.43 1177,954.43 1084,1047.43 904,1047.43 839,1112.43 839,1258.43 807,1290.43 729,1290.43 711,1272.43 681,1272.43 674,1279.43 674,1372.43 678,1376.43 808,1376.43 844,1412.43 844,1609.43 830,1623.43
RoutingVias ThermalPadVias [IsVia and InAnyComponent] p1: holewidth=7.87 width=19.68 viastyle="Through Hole" minholewidth=5 minwidth=13 maxholewidth=12.99 maxwidth=23.62
RoutingVias [All] p2: holewidth=12.2 width=22.4 viastyle="Through Hole" minholewidth=5.9 minwidth=14 maxholewidth=20 maxwidth=40
SMDToCorner [All] p1: distance=25000
SilkToBoardRegionClearance [Not ((IsComment or IsDesignator) And (Hide <> 'False')) and not InRegion(1000,500,4000,800)] p1:
SilkToSilkClearance [All] p1: silktosilkclearance=3
SilkToSolderMaskClearance SilkToSolderMaskClearance_OutLine [istrack and InAnyComponent] p1: minsilkscreentomaskgap=0 clearancetoexposedcopper=FALSE
SilkToSolderMaskClearance SilkscreenOverComponentPads [IsPad] p2: minsilkscreentomaskgap=3 clearancetoexposedcopper=FALSE
SolderMaskExpansion [All] p1: expansion=0
Width [All] p1: maxlimit=100 minlimit=4 preferedwidth=6
13 further rules are at their usual default settings.

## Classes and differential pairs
net class Regions: 5V_IN 5V_IN_SW 5V_IN_USB GND NetD1_2 NetD2_2 SW2_CAP
net class 0.5A: RADAR_3V3 VCC_LD_SW_3V3
net class 0.85A: CB_PMIC_1V8 PMIC_1V8 RADAR_1V8 SW3
net class 2.5A: 5V_IN 5V_IN_SW 5V_IN_USB CB_PMIC_1V0 NetD1_2 NetD2_2 PMIC_1V0 RADAR_1P0_RF1 RADAR_1P0_RF2 RADAR_VOUT_PA SW2 USB_5V
net class LVDS: NetJ1_28 NetJ1_30 NetJ1_34 NetJ1_36 NetJ1_40 NetJ1_42 NetJ1_46 NetJ1_48 NetJ2_21 NetJ2_23 NetJ2_27 NetJ2_29 NetJ2_39 NetJ2_41 NetJ6_20 NetJ6_22 NetJ6_26 NetJ6_28 NetJ6_32 NetJ6_34 NetJ6_38 NetJ6_40 NetJ6_44 NetJ6_46 NetJ6_50 NetJ6_52 NetJ6_56 NetJ6_58 RADAR_LVDS_0M RADAR_LVDS_0P RADAR_LVDS_1M RADAR_LVDS_1P RADAR_LVDS_2M RADAR_LVDS_2P RADAR_LVDS_3M RADAR_LVDS_3P RADAR_LVDS_CLKM RADAR_LVDS_CLKP RADAR_LVDS_FRCLKM RADAR_LVDS_FRCLKP RADAR_LVDS_VALIDM RADAR_LVDS_VALIDP
net class 1A: CB_PMIC_1V2 PMIC_1V2 RADAR_1V2 SW1
pad class "Mounting Holes PADS": Free-TH9
net class "Diff Pairs": NetJ1_28 NetJ1_30 NetJ1_34 NetJ1_36 NetJ1_40 NetJ1_42 NetJ1_46 NetJ1_48 RADAR_LVDS_0M RADAR_LVDS_0P RADAR_LVDS_1M RADAR_LVDS_1P RADAR_LVDS_CLKM RADAR_LVDS_CLKP RADAR_LVDS_FRCLKM RADAR_LVDS_FRCLKP
component class Logo: Logo1 Logo5
component class FiducialMark: FID1 FID2 FID3 FID4 FID5 FID6
component class Label: LBL1
component class PROC073D_Decoupling_caps: C1 C2 C3 C4 C5 C6 C7 C8 C9 C10 C11 C12 C13 C14 C15 C16 C17 C18 C19 C20 C21 C22 C23 C24 C25 C26 C27 C28 C29 C30 C64 C76 C77 C78 C79 C80 C81 C82 C83 C88 C89 C100 C101 C102 C103 C104 L1 L2 L3 L7 R1
component class PROC073D_EVM_Hardware: "CAUTION HOT SURFACE1" FID1 FID2 FID3 FID4 FID5 FID6 LBL1 Logo1 Logo2 LOGO3 Logo4 Logo5 ZZ1 ZZ2 ZZ3 ZZ4 ZZ5
component class PROC073D_HD_Connector_60Pin: J1 J2 R4 R5 R6 R7 R8 R9 R10 R11 R12 R13 R15 R16 R17 R18 R19 R20 R21 R22 R23 R24 R26 R27 R28 R30 R31 R32 R33 R34 R35 R36 R37 R38 R39 R40 R41 R42 R52 R53 R58 R59 R60 R61 R62 R63 R64 R65 R66 R67 R124 R125 R126 R127 R128 R129 R130 R131 R132 R133 R134 R135 R136 R137 R140 TP14
component class PROC073D_IWR6843_Chip: C31 C32 C33 R72 R73 R74 R75 R76 R77 R150 R152 R153 R154 R155 R156 R169 TP2 TP3 TP4 TP5 TP6 TP7 U1 Y1
component class PROC073D_Can_Interface: C37 C38 C39 C40 C41 C42 C43 J3 J4 R3 R68 R69 R70 R71 R78 R79 R80 R81 R82 R83 R84 R85 R86 R87 R88 R89 R216 U5 U12 U13
component class PROC073D_QSPI_Flash_section: C34 C35 R43 R44 R45 R46 R47 R48 R49 R50 R51 U2
component class PROC073D_Temp_Current_sensor: C36 C57 C58 C59 C63 C65 R2 R14 R25 R29 R54 R55 R56 R57 R94 R101 R103 R104 R105 R106 R107 R108 R109 R110 R111 R112 R113 R114 R115 R116 R117 R139 R142 R143 R144 R145 R146 R147 R151 R157 R158 R159 R160 R161 R162 U3 U6 U7 U8 U10 U11
net class "TX and RX": RX1 RX2 RX3 RX4 TX1 TX2 TX3
component class AssemblyNote: ZZ1 ZZ2 ZZ3 ZZ4 ZZ5
net class Flash: RADAR_QSPI_CS RADAR_QSPI_D0 RADAR_QSPI_D1 RADAR_QSPI_D2 RADAR_QSPI_D3 RADAR_QSPI_SCLK
component class PROC073D_Flash_USB_To_UART: C44 C45 C46 C47 C48 C49 C50 C51 C84 C85 C86 D1 D2 D4 FL1 FL2 J5 L9 L10 LD1 R90 R91 R92 R93 R95 R96 R97 R98 R99 R100 R102 R118 R119 R120 R121 TP1 TP8 U14 U15 U16
component class PROC073D_HD_DCA_Conn: C52 C53 C92 C93 C94 C95 C96 C97 D5 D7 J6 LD2 LD4 Q1 R122 R123 R138 R141 R148 R149 R163 R164 R165 R166 R167 R168 R170 R171 R212 R213 R214 R215 R217 R218 R219 R220 R221 R222 R223 R224 R225 R226 R227 R228 R229 R230 S2 S3 SW1 SW2 TP12 TP13 U17
component class PROC073D_PMIC: C54 C55 C56 C60 C61 C62 C66 C67 C68 C69 C70 C71 C72 C73 C74 C75 C87 C90 C91 C98 C99 Case D3 D6 FL3 FL4 L4 L5 L6 L8 L11 L12 LD3 Q2 R172 R173 R174 R175 R176 R177 R178 R179 R180 R181 R182 R183 R184 R185 R186 R187 R188 R189 R190 R191 R192 R193 R194 R195 R196 R197 R198 R199 R200 R201 TP9 TP10 TP11 U4 U9
component class PROC073D_SOP_Ctrl: R202 R203 R204 R205 R206 R207 R208 R209 R210 R211 S1
differential pair NewDifferentialPair21: +NetJ6_38 -NetJ6_40
differential pair NewDifferentialPair20: +RADAR_LVDS_2P -RADAR_LVDS_2M
differential pair NewDifferentialPair19: +NetJ2_23 -NetJ2_21
differential pair NewDifferentialPair18: +NetJ6_32 -NetJ6_34
differential pair NewDifferentialPair17: +RADAR_LVDS_3P -RADAR_LVDS_3M
differential pair NewDifferentialPair16: +NetJ2_29 -NetJ2_27
differential pair NewDifferentialPair15: +NetJ2_41 -NetJ2_39
differential pair NewDifferentialPair14: +RADAR_LVDS_VALIDP -RADAR_LVDS_VALIDM
differential pair NewDifferentialPair13: +NetJ6_20 -NetJ6_22
differential pair NewDifferentialPair12: +NetJ6_28 -NetJ6_26
differential pair NewDifferentialPair11: +NetJ6_44 -NetJ6_46
differential pair NewDifferentialPair10: +NetJ6_52 -NetJ6_50
differential pair NewDifferentialPair9: +NetJ6_58 -NetJ6_56
differential pair NewDifferentialPair8: +NetJ1_30 -NetJ1_28
differential pair NewDifferentialPair7: +NetJ1_36 -NetJ1_34
differential pair NewDifferentialPair6: +NetJ1_42 -NetJ1_40
differential pair NewDifferentialPair5: +NetJ1_48 -NetJ1_46
differential pair NewDifferentialPair4: +RADAR_LVDS_FRCLKM -RADAR_LVDS_FRCLKP
differential pair NewDifferentialPair3: +RADAR_LVDS_CLKM -RADAR_LVDS_CLKP
differential pair NewDifferentialPair2: +RADAR_LVDS_1M -RADAR_LVDS_1P
differential pair NewDifferentialPair1: +RADAR_LVDS_0M -RADAR_LVDS_0P

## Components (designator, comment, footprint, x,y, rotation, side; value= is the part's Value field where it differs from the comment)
C1 "CGA5L1X7R0J226M160AC" 1206_180 1230.15,775.38 r180 bottom value=22uF
C2 "CGA5L1X7R0J226M160AC" 1206_180 1021.11,2061.53 r270 bottom value=22uF
C3 "CGA5L1X7R0J226M160AC" 1206_180 882.8,1740.98 r90 bottom value=22uF
C4 "GCM155R71C224KE02D" 0402L 1374.59,1473.43 r270 top value=0.22uF
C5 "GCM155R71C224KE02D" 0402L 1419.18,1147.84 r180 top value=0.22uF
C6 "CGA2B3X7R1H473K050BB" 0402L 1325,1206.43 r0 bottom value=0.047uF
C7 "C0805C106M8RACTU" 0805_HV 1542.32,1662.55 r180 bottom value=10uF
C8 "C0805C106M8RACTU" 0805_HV 1542.32,1752.76 r180 bottom value=10uF
C9 "GCM155R71C224KE02D" 0402L 1200,1061.43 r90 bottom value=0.22uF
C10 "GCM155R71C224KE02D" 0402L 960.59,1266.43 r180 bottom value=0.22uF
C11 "GCM155R71C224KE02D" 0402L 991.8,1460.26 r270 bottom value=0.22uF
C12 "GCM155R71C224KE02D" 0402L 1190.24,1421.11 r180 bottom value=0.22uF
C13 "C0805C106M8RACTU" 0805_HV 1186.86,1481.66 r180 bottom value=10uF
C14 "GCM155R71C224KE02D" 0402L 1505.59,1146.43 r180 top value=0.22uF
C15 "C0805C106M8RACTU" 0805_HV 1615,1141.43 r270 top value=10uF
C16 "GCM155R71C224KE02D" 0402L 1163.59,916.43 r90 top value=0.22uF
C17 "GCM188R70J225KE22D" 0603 800.59,1276.43 r0 top value=2.2uF
C18 "GCM188R71C105KA64D" 0603 1436.78,1072.84 r180 top value=1uF
C19 "GCM155R71C224KE02D" 0402L 1025.8,1460.26 r270 bottom value=0.22uF
C20 "GCM155R71C224KE02D" 0402L 1359.36,1547.4 r180 bottom value=0.22uF
C21 "GCM155R71C224KE02D" 0402L 806.59,1227.43 r0 top value=0.22uF
C22 "GCM188R71C105KA64D" 0603 1440.59,1216.43 r180 top value=1uF
C23 "C0805C106M8RACTU" 0805_HV 999.85,1577.78 r90 bottom value=10uF
C24 "C0805C106M8RACTU" 0805_HV 1357.15,1464.94 r180 bottom value=10uF
C25 "GCM155R71C104KA55D" 0402L 875.59,1006.43 r0 top value=0.1uF
C26 "GCM155R71C104KA55D" 0402L 1134.5,992.43 r90 top value=0.1uF
C27 "GCM188R70J225KE22D" 0603 810.59,1056.43 r0 top value=2.2uF
C28 "GCM155R71C224KE02D" 0402L 850.59,1361.43 r0 top value=0.22uF
C29 "GCM155R71C224KE02D" 0402L 980.59,1206.43 r270 bottom value=0.22uF
C30 "GCM155R71E103KA37D" 0402L 1103,1016.43 r270 bottom value=0.01uF
C31 "GRM033C71A104KE14D" 0201#1 1049.59,1113.43 r90 bottom value=0.1uF
C32 "GJM1555C1H4R7BB01D" 0402L 1435.59,966.43 r90 top value=4.7pF
C33 "GJM1555C1H4R7BB01D" 0402L 1315.59,871.43 r180 top value=4.7pF
C34 "CGA2B3X7R1H104K050BB" 0402L 635.7,618.33 r180 top value=0.1uF
C35 "GCM188R71C105KA64D" 0603 647.51,552.29 r180 top value=1uF
C36 "CGA2B3X7R1H104K050BB" 0402L 900,646.43 r90 bottom value=0.1uF
C37 "C0402C104K8RACTU" 0402L 369.48,341.37 r90 bottom value=0.1uF
C38 "C0402C104K8RACTU" 0402L 223.71,428.27 r270 bottom value=0.1uF
C39 "GCM155R71H472KA37D" 0402L 243.19,263.8 r180 bottom value=4700pF
C40 "C0402C104K8RACTU" 0402L 238.73,135.39 r90 bottom value=0.1uF
C41 "C0402C104K8RACTU" 0402L 211.15,205.08 r180 bottom value=0.1uF
C42 "GCM155R71H472KA37D" 0402L 100.49,119.38 r0 bottom value=4700pF
C43 "C0402C104K8RACTU" 0402 682.22,418.42 r90 top value=0.1uF
C44 "GRM033R6YA104KE14D" "FP-GRM033R6YA104KE14D_0201 (0603 Metric)-IPC_C" 1886.12,-6.42 r180 top
C45 "GRM033R6YA104KE14D" "FP-GRM033R6YA104KE14D_0201 (0603 Metric)-IPC_C" 1886.12,19.89 r180 top
C46 "CL05A106MP5NUNC" 0402_070 1790.76,-217.04 r270 top value=10uF
C47 "CL05A106MP5NUNC" 0402_070 1829.82,-217.04 r90 top value=10uF
C48 "GRM033R6YA104KE14D" "FP-GRM033R6YA104KE14D_0201 (0603 Metric)-IPC_C" 1892.6,234.77 r270 top
C49 "GRM033R6YA104KE14D" "FP-GRM033R6YA104KE14D_0201 (0603 Metric)-IPC_C" 1630.48,144.92 r180 top
C50 "GRM033R6YA104KE14D" "FP-GRM033R6YA104KE14D_0201 (0603 Metric)-IPC_C" 1605.7,313.9 r180 top
C51 "CL03A105MO3NRNH" FP-CL03A105MO3NRNH_0201-IPC_C 1710.29,234.43 r270 top
C52 "GRM033R6YA104KE14D" "FP-GRM033R6YA104KE14D_0201 (0603 Metric)-IPC_C" 639.02,1042.72 r0 top
C53 "GRM033R6YA104KE14D" "FP-GRM033R6YA104KE14D_0201 (0603 Metric)-IPC_C" 571.56,999.1 r0 top
C54 "TMK063CG391JT-F" "FP-TMK063CG391JT-F_0201 (0603 Metric)-IPC_C" 816.81,178.5 r180 top
C55 "TMK063CG391JT-F" "FP-TMK063CG391JT-F_0201 (0603 Metric)-IPC_C" 1221.31,125 r0 top
C56 "TMK063CG391JT-F" "FP-TMK063CG391JT-F_0201 (0603 Metric)-IPC_C" 821.11,435.45 r180 top
C57 "CGA2B3X7R1H104K050BB" 0402L 1221.73,322.88 r0 top value=0.1uF
C58 "CGA2B3X7R1H104K050BB" 0402L 545.37,1700.76 r0 bottom value=0.1uF
C59 "CGA2B3X7R1H104K050BB" 0402L 810.31,631.74 r0 bottom value=0.1uF
C60 "TMK063CG391JT-F" "FP-TMK063CG391JT-F_0201 (0603 Metric)-IPC_C" 1158.44,442.7 r0 top
C61 "CL05A226MQ5N6J8" "FP-CL05A226MQ5N6J8_0402 (1005 Metric)-IPC_C" 986.51,105.67 r90 top
C62 "CL05A226MQ5N6J8" "FP-CL05A226MQ5N6J8_0402 (1005 Metric)-IPC_C" 1016.73,105.67 r90 top
C63 "CGA2B3X7R1H104K050BB" 0402L 898.74,1109.62 r180 bottom value=0.1uF
C64 "CGA5L1X7R0J226M160AC" 1206_180 509.74,1895.02 r0 bottom value=22uF
C65 "CGA2B3X7R1H104K050BB" 0402L 475,2126.43 r0 bottom value=0.1uF
C66 "CL05A226MQ5N6J8" "FP-CL05A226MQ5N6J8_0402 (1005 Metric)-IPC_C" 983.92,559.16 r270 top
C67 "CL05A226MQ5N6J8" "FP-CL05A226MQ5N6J8_0402 (1005 Metric)-IPC_C" 1015.86,559.16 r270 top
C68 "LMK063BJ224MP-F" 0201_033L 1112.94,326.14 r270 top value=0.22uF
C69 "CL10B105KQ8NNNC" 0603 760.98,719.45 r270 top value=1uF
C70 "C0603C104J5RACTU" 0603 708.74,1036.43 r90 top value=0.1uF
C71 "CGA2B3X7S2A102K050BB" 0402 933.74,916.43 r270 top value=1000pF
C72 "CL05A106MP5NUNC" 0402_070 1031.96,452.29 r180 top value=10uF
C73 "CL05A106MP5NUNC" 0402_070 1031.68,202.29 r180 top value=10uF
C74 "CL05A106MP5NUNC" 0402_070 969.08,452.29 r0 top value=10uF
C75 "CL05A106MP5NUNC" 0402_070 969.08,202.29 r0 top value=10uF
C76 "GCM32ER71C226KE19L" 1210_280 1417.84,1866.1 r0 bottom value=22uF
C77 "GCM21BR71A106KE22L" 0805_HV 1392.88,1975.36 r0 bottom value=10uF
C78 "GCM32ER71C226KE19L" 1210_280 1138.04,1849.51 r90 bottom value=22uF
C79 "GCM21BR71A106KE22L" 0805_HV 1029.97,1824.55 r90 bottom value=10uF
C80 "GCM32ER71C226KE19L" 1210_280 799.39,1586.85 r0 bottom value=22uF
C81 "GCM21BR71A106KE22L" 0805_HV 730.68,1895.09 r0 bottom value=10uF
C82 "GCM32ER71C226KE19L" 1210_280 1118.27,527.14 r0 bottom value=22uF
C83 "GCM21BR71A106KE22L" 0805_HV 1103.01,650.54 r0 bottom value=10uF
C84 "GCM155C71A474KE36D" 0402L 1751.34,191.02 r0 top value=0.47uF
C85 "LMK105B7224KVHF" 0402S 1751.55,154.66 r0 top value=0.22uF
C86 "GRT188R61A106KE13D" 0603S 1873.14,-164.46 r0 top value=10uF
C87 "GRT188R61A106KE13D" 0603S 632.15,961.78 r0 top value=10uF
C88 "GRT188R61A106KE13D" 0603S 1062.17,967.51 r270 bottom value=10uF
C89 "LMK105B7224KVHF" 0402S 1136.85,982.08 r90 bottom value=0.22uF
C90 "CL05A226MQ5N6J8" "FP-CL05A226MQ5N6J8_0402 (1005 Metric)-IPC_C" 956.3,105.67 r90 top
C91 "CL05A226MQ5N6J8" "FP-CL05A226MQ5N6J8_0402 (1005 Metric)-IPC_C" 1048.94,105.67 r90 top
C92 "GCM155C71A474KE36D" 0402L 1590.29,428.95 r180 top value=0.47uF
C93 "GRT155C81A105KE01D" 0402L 1590.29,395.27 r180 top value=1uF
C94 "LMK105B7224KVHF" 0402S 1590.29,361.6 r180 top value=0.22uF
C95 "GRT188R61A106KE13D" 0603S 1716.14,445.98 r270 top value=10uF
C96 "GRT188R61A106KE13D" 0603S 1763.58,445.98 r270 top value=10uF
C97 "GRT188R61A106KE13D" 0603S 1668.5,445.98 r270 top value=10uF
C98 "CL05A226MQ5N6J8" "FP-CL05A226MQ5N6J8_0402 (1005 Metric)-IPC_C" 954.18,559.16 r270 top
C99 "CL05A226MQ5N6J8" "FP-CL05A226MQ5N6J8_0402 (1005 Metric)-IPC_C" 1045.65,559.16 r270 top
C100 "CL05A226MQ5N6J8" "FP-CL05A226MQ5N6J8_0402 (1005 Metric)-IPC_C" 1153.91,1349.86 r270 bottom
C101 "CL05A226MQ5N6J8" "FP-CL05A226MQ5N6J8_0402 (1005 Metric)-IPC_C" 1087.5,1364.49 r270 bottom
C102 "CL05A226MQ5N6J8" "FP-CL05A226MQ5N6J8_0402 (1005 Metric)-IPC_C" 1414.23,1432.41 r270 top
C103 "CL05A226MQ5N6J8" "FP-CL05A226MQ5N6J8_0402 (1005 Metric)-IPC_C" 1306.03,1552.77 r90 top
C104 "CL05A226MQ5N6J8" "FP-CL05A226MQ5N6J8_0402 (1005 Metric)-IPC_C" 1352.23,1536.08 r0 top
"CAUTION HOT SURFACE1" "CAUTION HOT SURFACE" IEC_HotSurface_Small 579.8,2104.07 r0 top
D1 "NSR20F30NXT5G" DSN2_0603 1931.61,-260.55 r0 top value=30V
D2 "NSR20F30NXT5G" DSN2_0603 1778.12,296.35 r90 top value=30V
D3 "TLMY1000-GS08" TLMx1000_Yellow 657.08,104.57 r180 top value=Yellow
D4 "APHHS1005CGCK" APHHS1005_Green 1604.25,-62.83 r270 top value=Green
D5 "APHHS1005CGCK" APHHS1005_Green 345.96,1112.54 r90 top value=Green
D6 "APHHS1005CGCK" APHHS1005_Green 1273.45,175.99 r180 top value=Green
D7 "APHHS1005CGCK" APHHS1005_Green 1684.74,1093 r90 top value=Green
FID1 "Fiducial" Fiducial10-20 294.16,2105.3 r90 top
FID2 "Fiducial" Fiducial10-20 2091.36,170.94 r90 bottom
FID3 "Fiducial" Fiducial10-20 314.16,71.44 r90 bottom
FID4 "Fiducial" Fiducial10-20 613.28,-116.48 r90 top
FID5 "Fiducial" Fiducial10-20 294.16,2102.8 r90 bottom
FID6 "Fiducial" Fiducial10-20 2091.36,170.94 r90 top
J1 "QSH-030-01-L-D-A" Samtec_QSH-030-01-X-D-A 1708.74,801.43 r0 bottom locked
J2 "QSH-030-01-L-D-A" Samtec_QSH-030-01-X-D-A 417.24,801.43 r0 bottom locked
J3 "M50-3930342" FP-M50-3930342_HDR3-MFG 47.76,757.43 r270 top
J4 "M50-3930342" FP-M50-3930342_HDR3-MFG 47.76,520.09 r270 top
J5 "105017-0001" CONN_105017-0001 2055.12,-106.96 r90 top
J6 "QSH-030-01-L-D-A" Samtec_QSH-030-01-X-D-A 1219.74,-77.86 r270 bottom locked
L1 "MPZ2012S101A" MPZ2012 1087.23,785.81 r270 bottom value="100 ohm"
L2 "MPZ2012S101A" MPZ2012 1171.01,1994.6 r0 bottom value="100 ohm"
L3 "MPZ2012S101A" MPZ2012 999.54,1700.28 r0 bottom value="100 ohm"
L4 "MCKK2012TR47M" "FP-MCKK2012TR47M_0805 (2012 Metric)-IPC_C" 904.85,127.26 r90 top
L5 "MCKK2012TR47M" "FP-MCKK2012TR47M_0805 (2012 Metric)-IPC_C" 1104.7,126.22 r90 top
L6 "MCKK2012TR47M" "FP-MCKK2012TR47M_0805 (2012 Metric)-IPC_C" 885.96,526.06 r270 top
L7 "MPZ2012S101A" MPZ2012 595.47,1801.73 r0 bottom value="100 ohm"
L8 "MCKK2012TR47M" "FP-MCKK2012TR47M_0805 (2012 Metric)-IPC_C" 1097.25,525.39 r270 top
L9 "BLM15PD300SZ1D" 0402L 1940.16,-191.63 r270 top
L10 "BLM15PD300SZ1D" 0402L 1694.33,297.06 r90 top
L11 "BLM15PD300SZ1D" 0402L 1937.18,111.24 r0 top
L12 "BLM15PD300SZ1D" 0402L 864.11,33.63 r0 top
LBL1 "THT-14-423-10" Label_650x200 342.38,1727.14 r90 top
Logo1 "Texas Instruments" TI_Stacked_Overlay_Small 1726.87,728.81 r0 top
Logo2 "CE Mark" CE_Mark_5mm 1000.93,207.61 r180 bottom
LOGO3 "FCC disclaimer" FCC_disclaimer 966.67,2181.36 r180 bottom (schematic designator Logo3)
Logo4 "WEEE logo" WEEE_Minimum 1823.8,225.64 r180 bottom
Logo5 "Texas Instruments" TI_Symbol_Overlay_Small 1839.14,-195.13 r180 bottom
Q1 "BSS123-7-F" FP-BSS123-7-F_SOT23-IPC_C 434.95,1130.26 r180 top
Q2 "BSS123" SOT-23 658.67,17.66 r180 top value=100V
R1 "MCT06030Z0000ZP500" 0603 1404.27,1630.9 r0 bottom value=0
R2 "CRCW040210K0FKED" 0402L 1215.81,505.56 r90 top value=10.0k
R3 "ERJ-2GE0R00X" 0402 415.17,203.79 r0 bottom value=0
R4 "CRCW02010000Z0ED" 0201_Silk 1424.97,615.63 r180 bottom value=0
R5 "CRCW02010000Z0ED" 0201_Silk 1425.43,507.55 r0 bottom value=0
R6 "CRCW02010000Z0ED" 0201_Silk 1425.43,576.84 r180 bottom value=0
R7 "CRCW02010000Z0ED" 0201_Silk 1614.76,626.86 r0 top value=0
R8 "CRCW02010000Z0ED" 0201_Silk 1425.43,542.19 r180 bottom value=0
R9 "CRCW02010000Z0ED" 0201_Silk 1443.74,650 r0 bottom value=0
R10 "CRCW02010000Z0ED" 0201_Silk 1844.67,642.24 r180 top value=0
R11 "CRCW02010000Z0ED" 0201_Silk 1614.76,666.94 r0 top value=0
R12 "CRCW02010000Z0ED" 0201_Silk 1614.76,707.02 r180 top value=0
R13 "CRCW02010000Z0ED" 0201_Silk 1932.36,659.47 r0 bottom value=0
R14 "CRCW040210K0FKED" 0402L 1301.47,524.81 r270 bottom value=10.0k
R15 "CRCW020120R0FNED" 0201_033#1 1889.86,606.18 r0 top value=20.0
R16 "CRCW02010000Z0ED" 0201_Silk 1964.4,801.14 r90 bottom value=0
R17 "CRCW020120R0FNED" 0201_033#1 1889.86,567.81 r0 top value=20.0
R18 "CRCW020120R0FNED" 0201_033#1 1614.76,747.1 r0 top value=20.0
R19 "CRCW020120R0FNED" 0201_033#1 1448.74,717.75 r0 bottom value=20.0
R20 "CRCW020120R0FNED" 0201_033#1 1383.28,733.93 r0 bottom value=20.0
R21 "CRCW020120R0FNED" 0201_033#1 1614.76,787.18 r0 top value=20.0
R22 "CRCW02010000Z0ED" 0201_Silk 1863.79,744.08 r180 top value=0
R23 "CRCW020120R0FNED" 0201_033#1 1443.74,753.93 r0 bottom value=20.0
R24 "CRCW02010000Z0ED" 0201_Silk 1863.79,779.08 r180 top value=0
R25 "CRCW02010000Z0ED" 0201#2 1229.01,617.73 r90 top value=0
R26 "CRCW020120R0FNED" 0201_033#1 1443.74,788.57 r0 bottom value=20.0
R27 "CRCW020120R0FNED" 0201_033#1 1448.74,823.21 r0 bottom value=20.0
R28 "CRCW020120R0FNED" 0201_033#1 1448.74,857.86 r0 bottom value=20.0
R29 "CRCW02010000Z0ED" 0201#2 1267.18,617.73 r90 top value=0
R30 "CRCW02010000Z0ED" 0201_Silk 1863.79,828.55 r180 top value=0
R31 "CRCW02010000Z0ED" 0201_Silk 1932.36,697.17 r0 bottom value=0
R32 "CRCW02010000Z0ED" 0201_Silk 1863.79,863.55 r180 top value=0
R33 "CRCW02010000Z0ED" 0201_Silk 1863.79,923.9 r180 top value=0
R34 "CRCW02010000Z0ED" 0201_Silk 1475,1113.43 r0 bottom value=0
R35 "CRCW02010000Z0ED" 0201_Silk 1863.79,961.88 r180 top value=0
R36 "CRCW02010000Z0ED" 0201_Silk 1845.35,680.05 r180 top value=0
R37 "CRCW02010000Z0ED" 0201_Silk 1515,1147.43 r0 bottom value=0
R38 "CRCW02010000Z0ED" 0201_Silk 1704.94,1250.43 r180 bottom value=0
R39 "CRCW02010000Z0ED" 0201_Silk 1863.79,1026.09 r180 top value=0
R40 "CRCW02010000Z0ED" 0201_Silk 1704.94,1288.81 r180 bottom value=0
R41 "CRCW02010000Z0ED" 0201_Silk 1863.79,1064.07 r180 top value=0
R42 "CRCW02010000Z0ED" 0201_Silk 1932.38,621.93 r180 bottom value=0
R43 "ERJ-2GE0R00X" 0402 553.88,546.45 r270 top value=0
R44 "CRCW040210K0FKED" 0402L 418.88,981.89 r90 top value=10.0k
R45 "CRCW020133R2FNED" 0201_Silk 403.88,538.85 r270 top value=33.2
R46 "CRCW020133R2FNED" 0201_Silk 503.88,902.76 r270 top value=33.2
R47 "CRCW020133R2FNED" 0201_Silk 453.88,902.76 r270 top value=33.2
R48 "CRCW020133R2FNED" 0201_Silk 453.88,538.85 r270 top value=33.2
R49 "CRCW040210K0FKED" 0402L 512.82,478.51 r0 top value=10.0k
R50 "CRCW040247K5FKED" 0402L 553.88,903.85 r270 top value=47.5k
R51 "CRCW020133R2FNED" 0201_Silk 503.88,538.85 r270 top locked value=33.2
R52 "CRCW040210K0FKED" 0402L 809.93,671.77 r0 bottom value=10.0k
R53 "CRCW040210K0FKED" 0402L 768.74,801.43 r90 bottom value=10.0k
R54 "CRCW040210K0FKED" 0402L 943.74,831.43 r90 bottom value=10.0k
R55 "CRCW02010000Z0ED" 0201#2 839.48,712.79 r0 bottom value=0
R56 "CRCW02010000Z0ED" 0201#2 843.74,786.43 r0 bottom value=0
R57 "CRCW04020000Z0ED" 0402 990.93,587.76 r270 bottom value=0
R58 "CRCW02010000Z0ED" 0201_Silk 1931.3,1008.12 r0 bottom value=0
R59 "CRCW02010000Z0ED" 0201_Silk 1931.3,1046.36 r0 bottom value=0
R60 "CRCW02010000Z0ED" 0201_Silk 1448.74,892.5 r180 bottom value=0
R61 "CRCW02010000Z0ED" 0201_Silk 1448.74,927.14 r180 bottom value=0
R62 "CRCW02010000Z0ED" 0201_Silk 1448.74,961.79 r180 bottom value=0
R63 "CRCW02010000Z0ED" 0201_Silk 1448.74,996.43 r180 bottom value=0
R64 "CRCW02010000Z0ED" 0201_Silk 1475,1079.43 r180 bottom value=0
R65 "CRCW02010000Z0ED" 0201_Silk 1980,1251.43 r270 bottom value=0
R66 "CRCW02010000Z0ED" 0201_Silk 1945,1251.43 r90 bottom value=0
R67 "CRCW02010000Z0ED" 0201_Silk 1910,1251.43 r90 bottom value=0
R68 "CRCW040261R9FKED" 0402L 243.19,306.93 r0 bottom value=61.9
R69 "CRCW02010000Z0ED" 0201_Silk 330.22,348.06 r270 bottom value=0
R70 "CRCW040210K0FKED" 0402L 411.23,251.6 r180 bottom value=10.0k
R71 "CRCW040210K0FKED" 0402L 411.23,285.9 r0 bottom value=10.0k
R72 "ERJ-2GE0R00X" 0402 782.12,1618.43 r0 top value=0
R73 "ERJ-2GE0R00X" 0402 810.31,1567.75 r0 top value=0
R74 "ERJ-2GE0R00X" 0402 800.59,1506.43 r0 top value=0
R75 "ERJ-2GE0R00X" 0402 704.13,1557.21 r0 top value=0
R76 "ERJ-2GE0R00X" 0402 1490,961.43 r90 top value=0
R77 "ERJ-2GE0R00X" 0402 1268.74,821.43 r180 top value=0
R78 "ERJ-2GE0R00X" 0402 528.88,281.56 r90 bottom value=0
R79 "CRCW040261R9FKED" 0402L 243.19,350.05 r180 bottom value=61.9
R80 "ERJ-2GE0R00X" 0402 538.88,281.56 r90 top value=0
R81 "CRCW040261R9FKED" 0402L 100.49,69.38 r180 bottom value=61.9
R82 "CRCW02010000Z0ED" 0201_Silk 201.99,142.09 r270 bottom value=0
R83 "CRCW040210K0FKED" 0402L 559.05,76.66 r270 top value=10.0k
R84 "CRCW040210K0FKED" 0402L 474.08,76.66 r90 top value=10.0k
R85 "ERJ-2GE0R00X" 0402 404.57,60.08 r180 top value=0
R86 "CRCW040261R9FKED" 0402L 100.49,169.38 r0 bottom value=61.9
R87 "ERJ-2GE0R00X" 0402 404.57,205.08 r180 top value=0
R88 "CRCW040210K0FKED" 0402L 638.24,416.35 r90 top value=10.0k
R89 "CRCW04024K70JNED" 0402 755.42,386.89 r270 top value=4.7k
R90 "RC0201FR-074K99L" 0201L 1789.23,99.82 r180 top value=4.99k
R91 "RC0201JR-070RL" "FP-RC0201JR-070RL_0201 (0603 Metric)-MFG" 1936.18,-81.82 r0 top
R92 "RC0201JR-070RL" "FP-RC0201JR-070RL_0201 (0603 Metric)-MFG" 1936.18,-108.48 r0 top
R93 "RC0201FR-074K99L" 0201L 1702.37,110.34 r270 top value=4.99k
R94 "CRCW040210K0FKED" 0402L 1303.87,624.42 r270 top value=10.0k
R95 "RR0306P-103-D" FP-RR0306P-103-D_0201-IPC_C 1750.79,110.34 r270 top
R96 "RC0201JR-070RL" "FP-RC0201JR-070RL_0201 (0603 Metric)-MFG" 1693.49,-163.08 r180 top
R97 "RC0201JR-070RL" "FP-RC0201JR-070RL_0201 (0603 Metric)-MFG" 1594.83,43.03 r180 top
R98 "RC0201JR-070RL" "FP-RC0201JR-070RL_0201 (0603 Metric)-MFG" 1594.83,13.91 r0 top
R99 "RC0201JR-07220RL" 0201L 1615.28,-124.7 r180 top value=220
R100 "RR0306P-103-D" FP-RR0306P-103-D_0201-IPC_C 1922.81,359.82 r0 top
R101 "CRCW040210K0FKED" 0402L 1182.13,505.53 r270 top value=10.0k
R102 "RR0306P-103-D" FP-RR0306P-103-D_0201-IPC_C 1397.73,274.12 r0 top
R103 "CRCW040210K0FKED" 0402L 1266.47,524.81 r90 bottom value=10.0k
R104 "CRCW040210K0FKED" 0402L 378.85,1558.68 r180 bottom value=10.0k
R105 "CRCW040210K0FKED" 0402L 378.85,1525.06 r180 bottom value=10.0k
R106 "CRCW040210K0FKED" 0402L 634.64,418.02 r180 bottom value=10.0k
R107 "CRCW040210K0FKED" 0402L 674.01,336.97 r0 bottom value=10.0k
R108 "CRCW02010000Z0ED" 0201#2 458.56,1752.5 r90 bottom value=0
R109 "CRCW02010000Z0ED" 0201#2 715,716.43 r0 bottom value=0
R110 "CRCW02010000Z0ED" 0201#2 497.17,1752.5 r90 bottom value=0
R111 "CRCW02010000Z0ED" 0201#2 715,681.43 r0 bottom value=0
R112 "CRCW040210K0FKED" 0402L 378.85,1653.12 r0 bottom value=10.0k
R113 "CRCW040210K0FKED" 0402L 378.85,1592.31 r0 bottom value=10.0k
R114 "CRCW040210K0FKED" 0402L 378.85,1491.43 r0 bottom value=10.0k
R115 "CRCW040210K0FKED" 0402L 636.16,695.69 r270 bottom value=10.0k
R116 "CRCW040210K0FKED" 0402L 634.64,454.23 r0 bottom value=10.0k
R117 "CRCW040210K0FKED" 0402L 634.64,381.8 r0 bottom value=10.0k
R118 "RC0201JR-07510RL" 0201L 1521.34,316.41 r180 top value=510
R119 "CRCW0201100KFKED" 0201L 1467.08,285.17 r90 top value=100k
R120 "CRCW0201100KFKED" 0201L 1432.23,285.17 r270 top value=100k
R121 "CRCW0402200RFKEDHP" FP-CRCW0402200RFKEDHP_0402-IPC_C 1438.41,169.94 r0 top
R122 "ERJ-2GE0R00X" 0402L 729.49,-47.51 r0 bottom value=0
R123 "RR0306P-103-D" FP-RR0306P-103-D_0201-IPC_C 622.73,1016.99 r180 top
R124 "CRCW020120R0FNED" 0201_033#1 658.74,1021.43 r180 bottom value=20.0
R125 "CRCW020120R0FNED" 0201_033#1 658.74,986.43 r180 bottom value=20.0
R126 "CRCW020120R0FNED" 0201_033#1 643.74,951.43 r180 bottom value=20.0
R127 "CRCW020120R0FNED" 0201_033#1 643.74,916.43 r180 bottom value=20.0
R128 "CRCW020120R0FNED" 0201_033#1 643.74,881.43 r180 bottom value=20.0
R129 "CRCW020120R0FNED" 0201_033#1 643.74,851.43 r180 bottom value=20.0
R130 "CRCW020120R0FNED" 0201_033#1 643.74,816.43 r180 bottom value=20.0
R131 "CRCW02010000Z0ED" 0201_Silk 260,890.5 r0 top value=0
R132 "CRCW020120R0FNED" 0201_033#1 643.74,781.43 r180 bottom value=20.0
R133 "CRCW02010000Z0ED" 0201_Silk 260,855.5 r0 top value=0
R134 "CRCW02010000Z0ED" 0201_Silk 260,804.68 r0 top value=0
R135 "CRCW02010000Z0ED" 0201_Silk 260,769.68 r0 top value=0
R136 "CRCW02010000Z0ED" 0201_Silk 260,696.43 r0 top value=0
R137 "CRCW02010000Z0ED" 0201_Silk 260,661.43 r0 top value=0
R138 "RR0306P-103-D" FP-RR0306P-103-D_0201-IPC_C 622.73,1065.29 r180 top
R139 "CRCW040210K0FKED" 0402L 955.18,1416.6 r90 bottom value=10.0k
R140 "CRCW02010000Z0ED" 0201_Silk 658.74,1056.43 r180 bottom value=0
R141 "RC0201JR-07510RL" 0201L 302.97,1105.85 r270 top value=510
R142 "CRCW040210K0FKED" 0402L 965,1336.43 r0 bottom value=10.0k
R143 "CRCW02010000Z0ED" 0201#2 883.92,1416.6 r90 bottom value=0
R144 "CRCW02010000Z0ED" 0201#2 833.74,1416.43 r90 bottom value=0
R145 "CRCW040210K0FKED" 0402L 798.74,1416.43 r270 bottom value=10.0k
R146 "CRCW040210K0FKED" 0402L 920.18,1416.6 r270 bottom value=10.0k
R147 "CRCW040210K0FKED" 0402L 965,1301.43 r180 bottom value=10.0k
R148 "CRCW020120R0FNED" 0201_033#2 1196.94,160.87 r270 bottom value=20.0
R149 "CRCW020120R0FNED" 0201_033#2 1234.31,160.87 r270 bottom value=20.0
R150 "CRCW040210K0JNED" 0402 1900,1119.34 r180 top value=10k
R151 "CRCW04020000Z0ED" 0402 977.93,695.88 r270 bottom value=0
R152 "CRCW040210K0FKED" 0402L 1795.94,622.55 r90 top value=10.0k
R153 "CRCW0402100KFKED" 0402L 1837.89,1288.13 r0 bottom value=100k
R154 "CRCW0402100KFKED" 0402L 1837.89,1254.19 r0 bottom value=100k
R155 "CRCW0402100KFKED" 0402L 1717.01,644.6 r90 top value=100k
R156 "CRCW0402100KFKED" 0402L 1230,976.43 r90 bottom value=100k
R157 "CRCW040210K0FKED" 0402L 475,2052.43 r180 bottom value=10.0k
R158 "CRCW040210K0FKED" 0402L 475,2086.43 r0 bottom value=10.0k
R159 "CRCW02010000Z0ED" 0201#2 429.4,1996.15 r180 bottom value=0
R160 "CRCW02010000Z0ED" 0201#2 429.4,1958.61 r180 bottom value=0
R161 "CRCW040210K0FKED" 0402L 870,2016.43 r0 bottom value=10.0k
R162 "CRCW040210K0FKED" 0402L 870,1981.43 r180 bottom value=10.0k
R163 "CRCW020120R0FNED" 0201_033#2 1271.67,160.87 r270 bottom value=20.0
R164 "CRCW020120R0FNED" 0201_033#2 1311.95,154.88 r270 bottom value=20.0
R165 "RR0306P-103-D" FP-RR0306P-103-D_0201-IPC_C 537.82,988.59 r270 top
R166 "CRCW020120R0FNED" 0201_033#2 1352.68,154.88 r270 bottom value=20.0
R167 "CRCW020120R0FNED" 0201_033#2 1390.77,144.03 r270 bottom value=20.0
R168 "CRCW020120R0FNED" 0201_033#2 1429.92,144.03 r270 bottom value=20.0
R169 "CRCW040210K0JNED" 0402 1900,1191.43 r180 top value=10k
R170 "CRCW020120R0FNED" 0201_033#2 1467.83,144.03 r270 bottom value=20.0
R171 "RC0201JR-07510RL" 0201L 526.8,1083.65 r180 top value=510
R172 "ERJ-2GEJ511X" 0402L 665.93,154.18 r180 top value=510
R173 "RC0402FR-073R83L" "FP-RC0402FR-073R83L_0402 (1005 Metric)-IPC_C" 854.61,173.45 r270 top
R174 "RC0201JR-07510RL" 0201L 1281.31,215.41 r0 top value=510
R175 "RC0402FR-073R83L" "FP-RC0402FR-073R83L_0402 (1005 Metric)-IPC_C" 1183.51,154.63 r180 top
R176 "RC0201FR-074K99L" 0201L 1123.96,284.16 r0 top value=4.99k
R177 "RC0201FR-074K99L" 0201L 1144.8,367.66 r0 top value=4.99k
R178 "RC0402FR-073R83L" "FP-RC0402FR-073R83L_0402 (1005 Metric)-IPC_C" 831.12,480.54 r90 top
R179 "ERJ-2GEJ511X" 0402L 776.61,-19.74 r180 top value=510
R180 "RC0201JR-070RL" "FP-RC0201JR-070RL_0201 (0603 Metric)-MFG" 878.14,289.16 r0 top
R181 "RC0201JR-070RL" "FP-RC0201JR-070RL_0201 (0603 Metric)-MFG" 877.8,313.66 r0 top
R182 "CRCW0402100KFKED" 0402L 776.61,14.84 r0 top value=100k
R183 "RC0402FR-073R83L" "FP-RC0402FR-073R83L_0402 (1005 Metric)-IPC_C" 1148.43,485.13 r90 top
R184 "CRCW040210K0JNED" 0402 1303.12,984.02 r180 bottom value=10k
R185 "CRCW04020000Z0ED" 0402 1303.12,1035.79 r180 bottom value=0
R186 "RC0201JR-071KL" 0201L 1265.29,262.61 r270 top value=1.0k
R187 "RC0201FR-074K99L" 0201L 1144.8,396.01 r0 top value=4.99k
R188 "RC0201FR-074K99L" 0201L 874.94,266.16 r180 top value=4.99k
R189 "RR0306P-103-D" FP-RR0306P-103-D_0201-IPC_C 1124.42,257.16 r0 top
R190 "RR0306P-103-D" FP-RR0306P-103-D_0201-IPC_C 881.46,375.35 r180 top
R191 "RCS06030000Z0EA" 0603 738.67,879.58 r90 top value=0
R192 "PMR18EZPFV2L00" 1206 1417.66,475.04 r90 top value=0.002
R193 "PMR18EZPFV2L00" 1206 794.24,372.27 r270 bottom value=0.002
R194 "RC0201FR-071K96L" 0201L 1234.41,262.61 r90 top value=1.96k
R195 "MCT06030Z0000ZP500" 0603 925.25,757.58 r180 top value=0
R196 "CRCW0402510RJNED" 0402 908.98,672.41 r90 top value=510
R197 "ERJ-2RKF1003X" 0402 848.74,831.43 r0 bottom value=100k
R198 "RC0201JR-070RL" "FP-RC0201JR-070RL_0201 (0603 Metric)-MFG" 783.5,86.51 r180 top
R199 "PMR18EZPFV2L00" 1206 551.66,1495.08 r180 bottom value=0.002
R200 "PMR18EZPFV2L00" 1206 884.81,961.78 r0 bottom value=0.002
R201 "CRCW0201100KFKED" 0201L 785.2,55.06 r0 top value=100k
R202 "ERJ-2GE0R00X" 0402L 911.88,-244.3 r180 top value=0
R203 "CRCW040210K0FKED" 0402L 1002.05,-230.73 r0 top value=10.0k
R204 "CRCW04027K87FKED" 0402L 1155.98,-223.19 r0 top value=7.87k
R205 "CRCW040282K5FKED" 0402L 1002.05,-264.45 r0 top value=82.5k
R206 "CRCW040210K0FKED" 0402L 920.56,-189.36 r270 top value=10.0k
R207 "CRCW04027K87FKED" 0402L 1155.98,-188.88 r0 top value=7.87k
R208 "CRCW040282K5FKED" 0402L 886.26,-189.36 r270 top value=82.5k
R209 "CRCW040210K0FKED" 0402L 1002.05,-152.92 r0 top value=10.0k
R210 "CRCW04027K87FKED" 0402L 1155.98,-153.92 r0 top value=7.87k
R211 "CRCW040282K5FKED" 0402L 1002.05,-187.4 r0 top value=82.5k
R212 "RC0201JR-07220RL" 0201L 1695.76,1157.61 r0 top value=220
R213 "RC0201JR-07220RL" 0201L 319.32,1352.92 r90 top value=220
R214 "RC0201JR-070RL" "FP-RC0201JR-070RL_0201 (0603 Metric)-IPC_C" 321.89,1178.31 r180 top
R215 "RR0306P-103-D" FP-RR0306P-103-D_0201-IPC_C 321.39,1208.04 r0 top
R216 "ERJ-2GE0R00X" 0402 516.22,80.59 r90 top value=0
R217 "CRCW02010000Z0ED" 0201_Silk 326.6,890.5 r180 top value=0
R218 "CRCW02010000Z0ED" 0201_Silk 326.6,855.5 r180 top value=0
R219 "CRCW02010000Z0ED" 0201_Silk 1797.27,736.22 r0 top value=0
R220 "CRCW02010000Z0ED" 0201_Silk 1796.85,787.38 r0 top value=0
R221 "CRCW02010000Z0ED" 0201_Silk 326.6,804.68 r180 top value=0
R222 "CRCW02010000Z0ED" 0201_Silk 326.6,769.68 r180 top value=0
R223 "CRCW02010000Z0ED" 0201_Silk 326.6,696.43 r180 top value=0
R224 "CRCW02010000Z0ED" 0201_Silk 326.6,661.43 r180 top value=0
R225 "CRCW02010000Z0ED" 0201_Silk 1797.27,820.68 r0 top value=0
R226 "CRCW02010000Z0ED" 0201_Silk 1796.85,871.84 r0 top value=0
R227 "CRCW02010000Z0ED" 0201_Silk 1797.27,916.04 r0 top value=0
R228 "CRCW02010000Z0ED" 0201_Silk 1796.85,970.18 r0 top value=0
R229 "CRCW02010000Z0ED" 0201_Silk 1796.85,1017.88 r0 top value=0
R230 "CRCW02010000Z0ED" 0201_Silk 1796.85,1072.37 r0 top value=0
S1 "218-6LPST" SW_218-6LPST 1394.21,-73.19 r90 top locked
S2 "B3U-1000P" SW_B3U-1000P 287.11,498.89 r0 top
S3 "B3U-1000P" SW_B3U-1000P 398.63,1274.97 r90 top
TP1 "TESTPOINT" TP_25MIL-SMT 1871.57,-99.27 r270 top
TP2 "TP_SM_1MM" TP_SM_1MM 692.27,1671.93 r90 top
TP3 "TP_SM_1MM" TP_SM_1MM 643.74,1625.33 r90 top
TP4 "TP_SM_1MM" TP_SM_1MM 716.44,1506.43 r90 top
TP5 "TP_SM_1MM" TP_SM_1MM 578.94,1593.59 r90 top
TP6 "TP_SM_1MM" TP_SM_1MM 1552,981.43 r90 top
TP7 "TP_SM_1MM" TP_SM_1MM 1450,886.43 r90 top
TP8 "TESTPOINT" TP_25MIL-SMT 1510.32,350.86 r180 top
TP9 "TESTPOINT" TP_25MIL-SMT 2015.61,111.24 r0 top
TP10 "TESTPOINT" TP_25MIL-SMT 1917.5,60.89 r90 top
TP11 "TESTPOINT" TP_VIA_060RND040 418.88,134.12 r180 top
TP12 "5001" Keystone5001 618.57,-244.3 r0 top
TP13 "5001" Keystone5001 750.27,-244.3 r0 top
TP14 "5001" Keystone5001 99.51,945.49 r0 top
U1 "IWR6843QAGABL" ABL0161B 1125.98,1281.05 r270 top locked
U2 "MX25V1635FZNQ" WSON-8L_6x5MM_EP 478.88,728.85 r270 top
U3 "TMP112AQDRLRQ1" DRL0006A 915.74,741.43 r270 bottom
U4 "LP87524JRNFRQ1" RNF0026C 1000.33,326.14 r0 top
U5 "TCAN1042HGVDQ1" D0008A_L 347.08,338.05 r180 top
U6 "INA226AIDGST" DGS0010A_L 1303.36,457.93 r270 top
U7 "INA226AIDGST" DGS0010A_L 542.07,1615.4 r0 bottom
U8 "INA226AIDGST" DGS0010A_L 725.86,551.56 r0 bottom
U9 "TPS22917DBVR" DBV0006A_N 838.74,881.43 r90 top
U10 "INA226AIDGST" DGS0010A_L 810.59,1241.43 r270 bottom
U11 "CAT24C08WI-GT3" SOIC-8 675,2051.43 r180 bottom
U12 "TCAN1042HGVDQ1" D0008A_L 217.94,130.08 r180 top
U13 "TS3A5018RSVR" RSV0016A 662.79,288.61 r0 top
U14 "CP2105-F01-GMR" FP-CP2105-F01-GMR_QFN24-EP-IPC_A 1735.81,-35.3 r180 top
U15 "TS5A23157RSER" RSE0010A 1882.76,301.64 r270 top
U16 "TPS2115ADRBR" DRB0008B 1565.35,227.53 r0 top
U17 "SN74LVC1G11DSFR" DSF0006A 553.57,1041.14 r180 top
Y1 "CX3225SA40000D0PTWCC" Kyocera_CX3225SA 1335.59,956.43 r90 top
ZZ1 "This Assembly Note is for PCB labels only" AssemblyNoteLabel -833.57,3288.93 r0 top
ZZ2 "These assemblies are ESD sensitive, ESD precautions shall be observed." AssemblyNote -831.16,3211.77 r0 top
ZZ3 "These assemblies must be clean and free from flux and all contaminants. Use of no clean flux is not acceptable." AssemblyNote -831.16,3124.96 r0 top
ZZ4 "These assemblies must comply with workmanship standards IPC-A-610 Class 2, unless otherwise specified." AssemblyNote -835.98,3033.33 r0 top
ZZ5 "INDICATION FOR COMPONENTS D* ARE GIVEN AT THEIR CATHODE SIDE." AssemblyNote -834.59,2945.73 r0 top

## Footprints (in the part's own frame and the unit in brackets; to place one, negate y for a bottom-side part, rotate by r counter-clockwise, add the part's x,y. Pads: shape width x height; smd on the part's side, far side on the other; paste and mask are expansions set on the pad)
0201#1 [mm] "Data from Kemet datasheet CC101_COM dated 7/28/11"
  rect 0.46x0.42 smd mask+0.048: 1(-0.33,0) 2(0.33,0)
  body extent -0.31,-0.16 0.31,0.16, height 0.26
0201#2 [mm] "Data from Kemet datasheet CC101_COM dated 7/28/11"
  rect 0.46x0.42 smd mask+0: 1(-0.33,0) 2(0.33,0)
  body extent -0.31,-0.16 0.31,0.16, height 0.26
0201_033#1 [mm] "SMD, 2-Leads, Height 0.33mm"
  rect 0.46x0.42 smd mask+0: 1(-0.33,0) 2(0.33,0)
  body extent -0.31,-0.16 0.31,0.16, height 0.33
0201_033#2 [mm] "SMD, 2-Leads, Height 0.33mm"
  rect 0.46x0.42 smd mask+0.048: 1(-0.33,0) 2(0.33,0)
  body extent -0.31,-0.16 0.31,0.16, height 0.33
0201_033L [mm] "0201"
  rect 0.36x0.32 smd mask+0.048: 1(-0.28,0) 2(0.28,0)
  body extent -0.31,-0.16 0.31,0.16, height 0.33
0201_Silk [mm] "Data from Kemet datasheet CC101_COM dated 7/28/11"
  rect 0.46x0.42 smd mask+0: 1(-0.33,0) 2(0.33,0)
  silkscreen extent -0.75,-0.4 0.75,0.4, body extent -0.31,-0.16 0.31,0.16, height 0.26
0201L [mm] "Data from Kemet datasheet CC101_COM dated 7/28/11"
  rect 0.36x0.32 smd mask+0.048: 1(-0.28,0) 2(0.28,0)
  body extent -0.31,-0.16 0.31,0.16, height 0.26
0402 [mm] "0402 from SM-752 data"
  rect 0.8x0.6 smd: 1(-0.6,0) 2(0.6,0)
  silkscreen extent -1.22,-0.52 1.22,0.52, body extent -0.55,-0.3 0.55,0.3, height 0.6
0402_070 [mil] "SMD, 2-Leads, Body 1.2x0.7mm, Height 0.7mm"
  rect 15x24 smd: 1(-20,0) 2(20,0)
  body extent -24,-14 24,14, height 28
0402L [mm] "0402 from SM-752 data"
  rect 0.6x0.5 smd: 1(-0.5,0) 2(0.5,0)
  body extent -0.55,-0.3 0.55,0.3, height 0.6
0402S [mil] "Based on C0402S footprint from PADS legacy"
  rect 15x24 smd: 1(-20,0) 2(20,0)
  body extent -22,-12 22,12, height 24
0603 [mm] "0603 from SM-752 data"
  rect 1x0.95 smd: 1(-0.8,0) 2(0.8,0)
  silkscreen extent -1.52,-0.69 1.52,0.69, body extent -0.87,-0.47 0.87,0.47, height 1
0603S [mil]
  rect 20x35 smd: 1(-30,0) 2(30,0)
  silkscreen extent -10,-17 10,17, body extent -34,-19 34,19, height 39
0805_HV [mil] "0805 with 30mil clearance between pads"
  rect 50x63 smd: 1(-40,0) 2(40,0)
  silkscreen extent -74,-40 74,40, body extent -43,-29 43,29, height 57
1206 [mm] "1206 from SM-752 data"
  rect 1.3x1.85 smd: 1(-1.45,0) 2(1.45,0)
  silkscreen extent -2.4,-1.21 2.4,1.21, body extent -1.7,-0.9 1.7,0.9, height 1.35
1206_180 [mm] "1206_180"
  rect 1.1x1.6 smd: 1(-1.7,0) 2(1.7,0)
  silkscreen extent -0.9,-1 0.9,1, body extent -1.75,-0.95 1.75,0.95, height 1.8
1210_280 [mm] "SMD, 2-Leads, Body 3.6x2.8mm, Height 2.8mm"
  rect 1.1x2.2 smd: 1(-1.65,0) 2(1.65,0)
  silkscreen extent -0.84,-1.4 0.84,1.4, body extent -1.8,-1.4 1.8,1.4, height 2.8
